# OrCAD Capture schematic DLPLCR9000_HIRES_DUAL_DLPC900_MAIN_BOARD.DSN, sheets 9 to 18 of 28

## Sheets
9 P21-Slave GPIOs: size A3
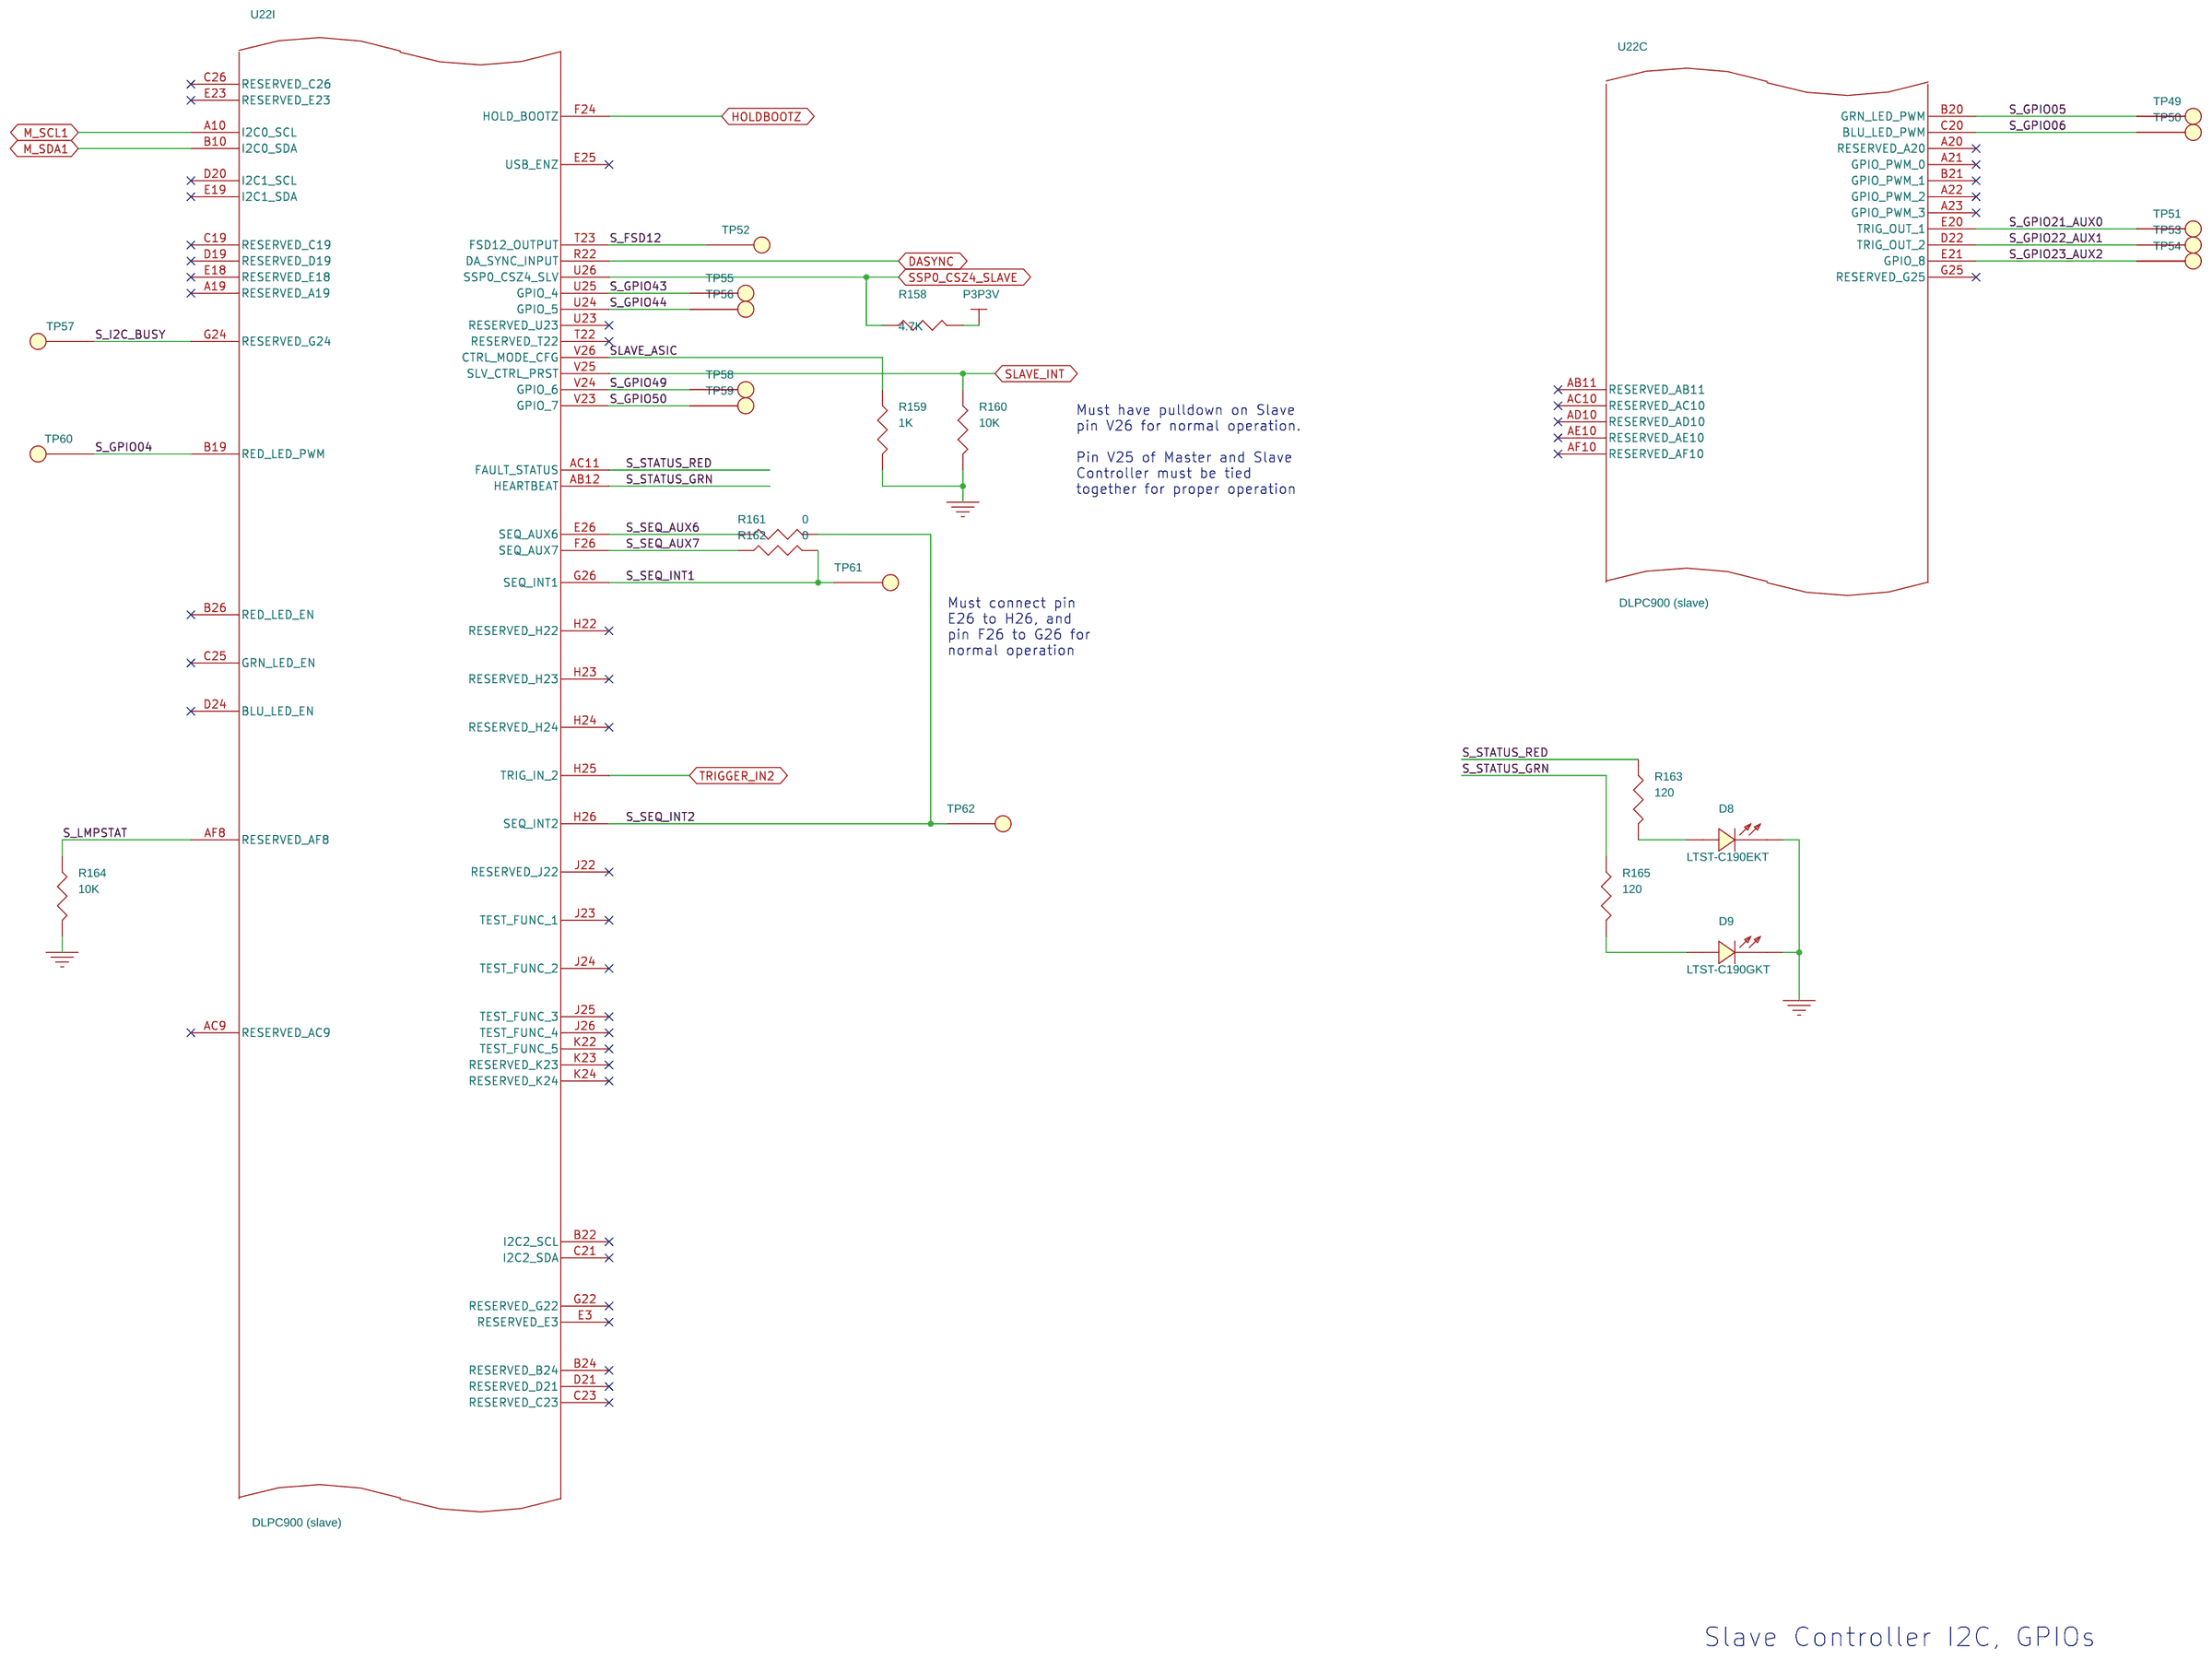
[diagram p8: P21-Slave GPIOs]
10 P19-Slave JTAG Osc Rst SSP: size A3
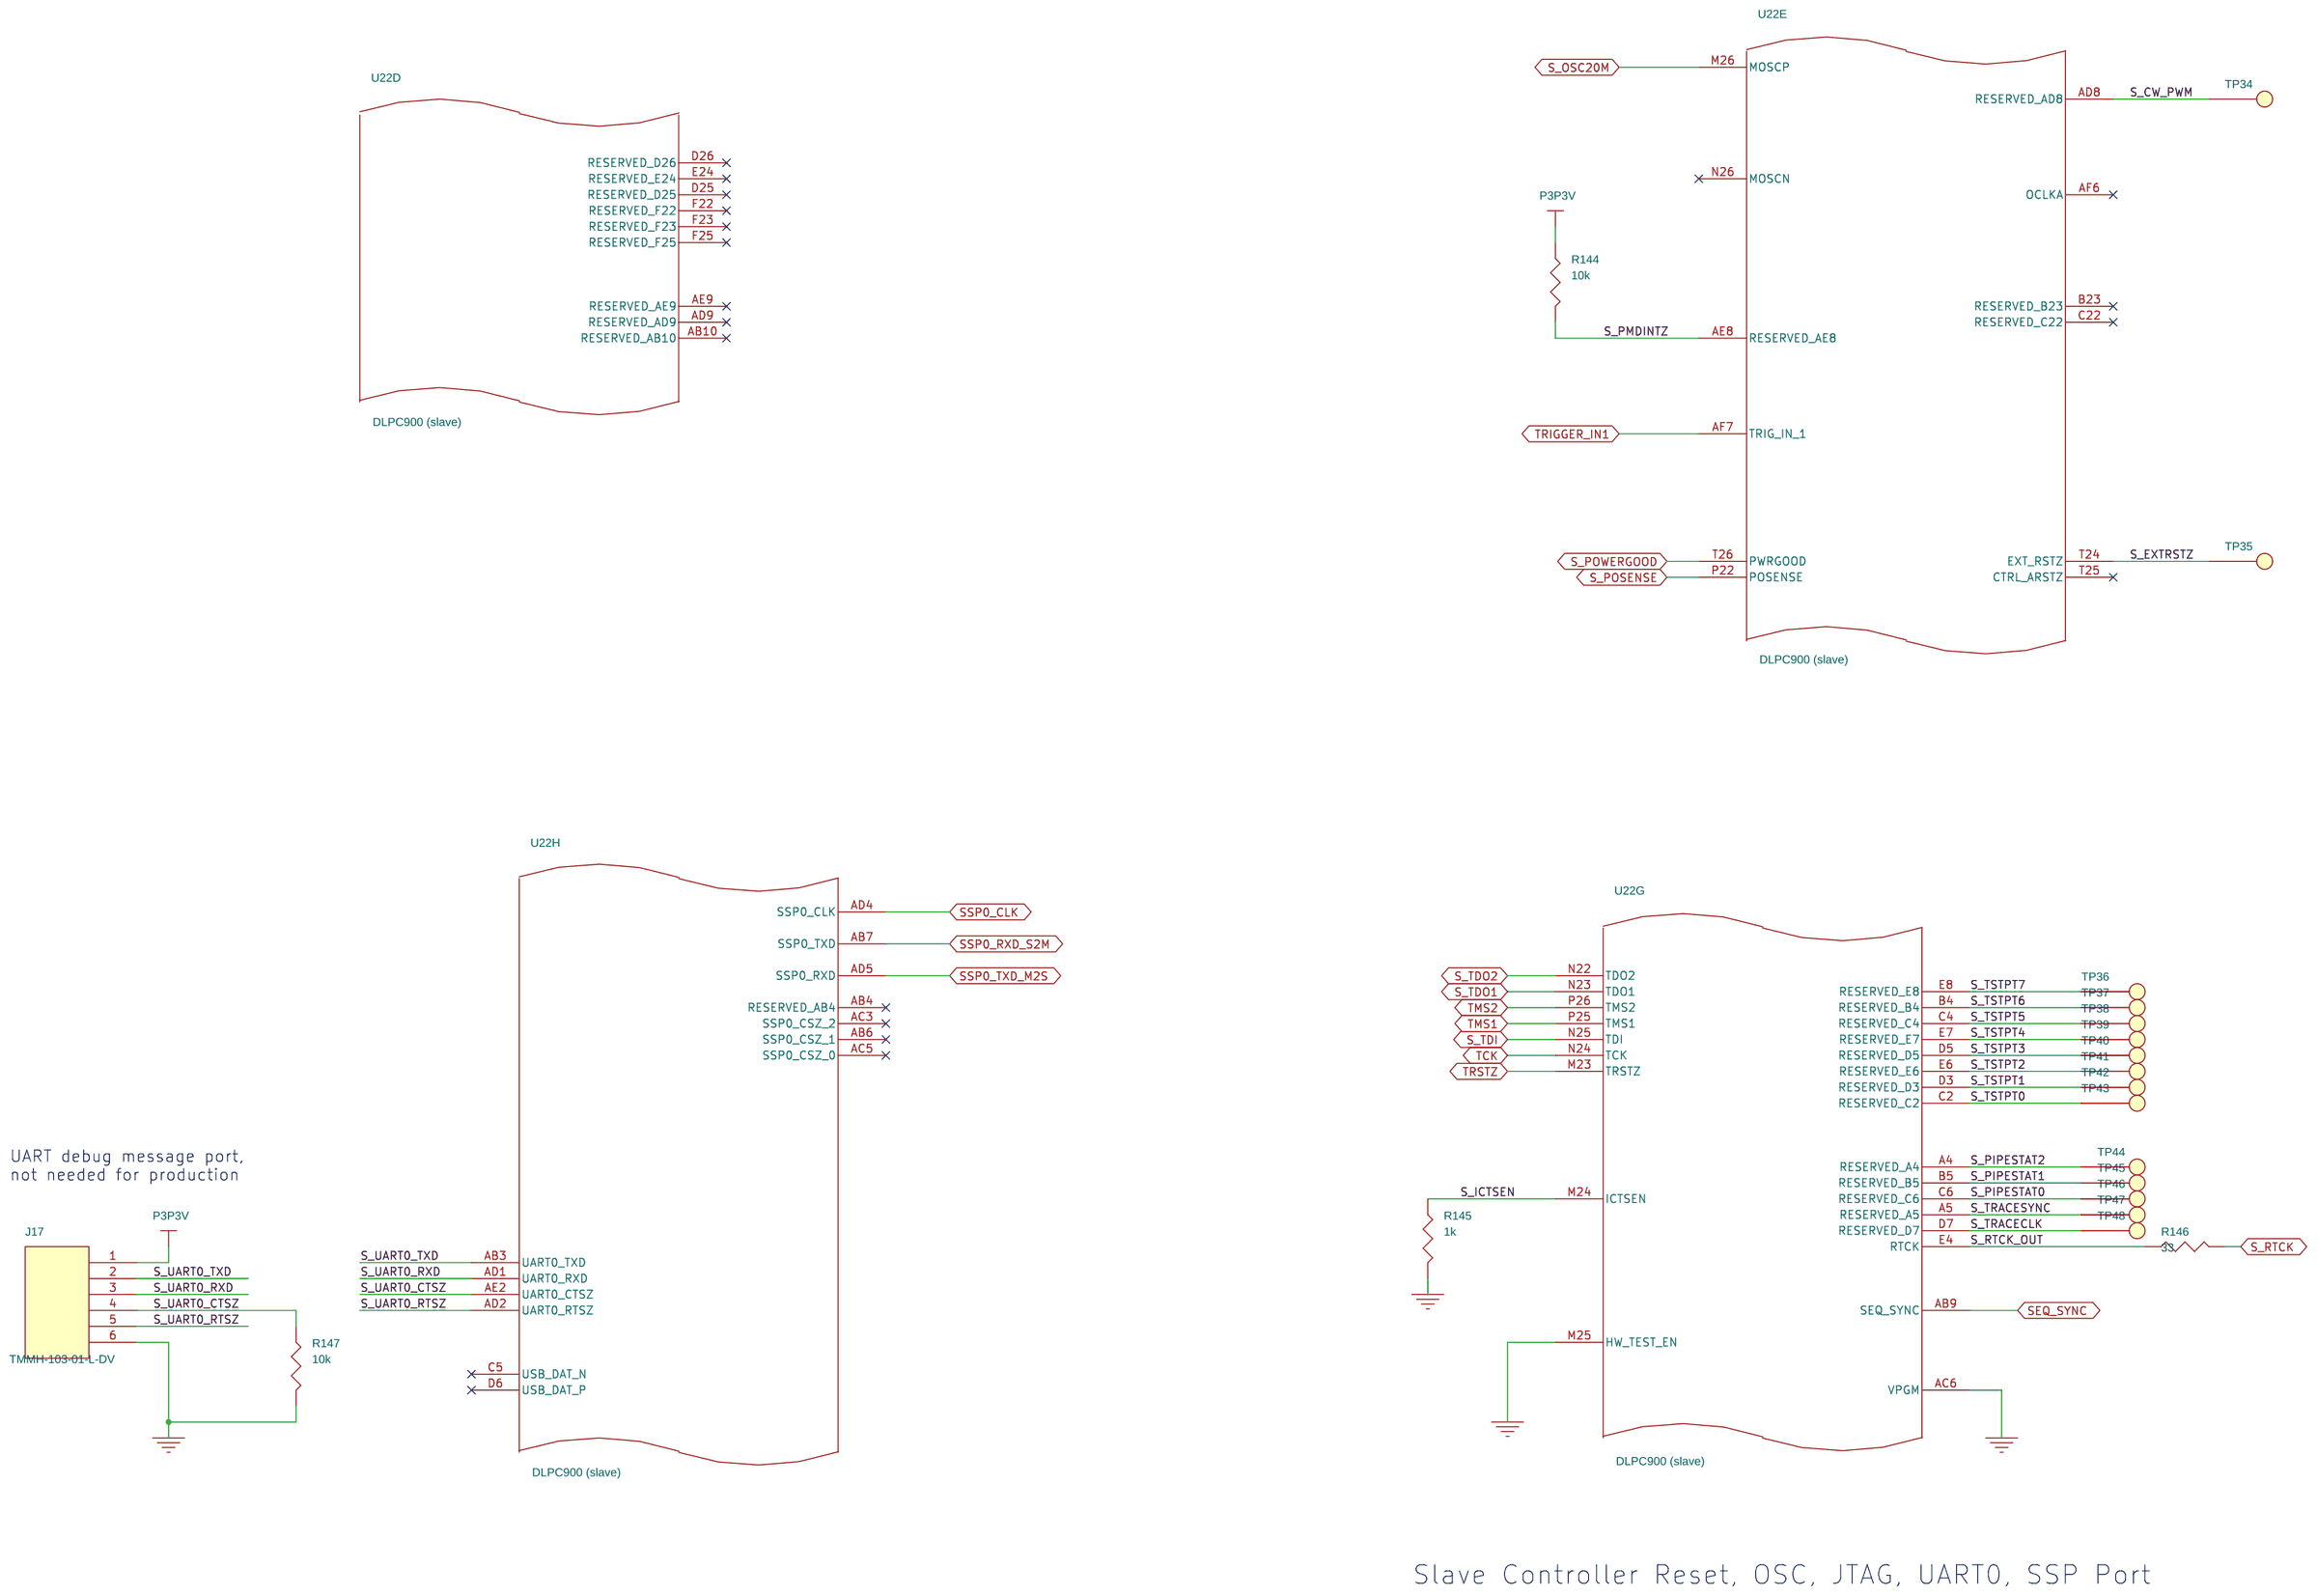
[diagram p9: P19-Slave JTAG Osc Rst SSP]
11 P18-Slave Vid DMD io: size A3
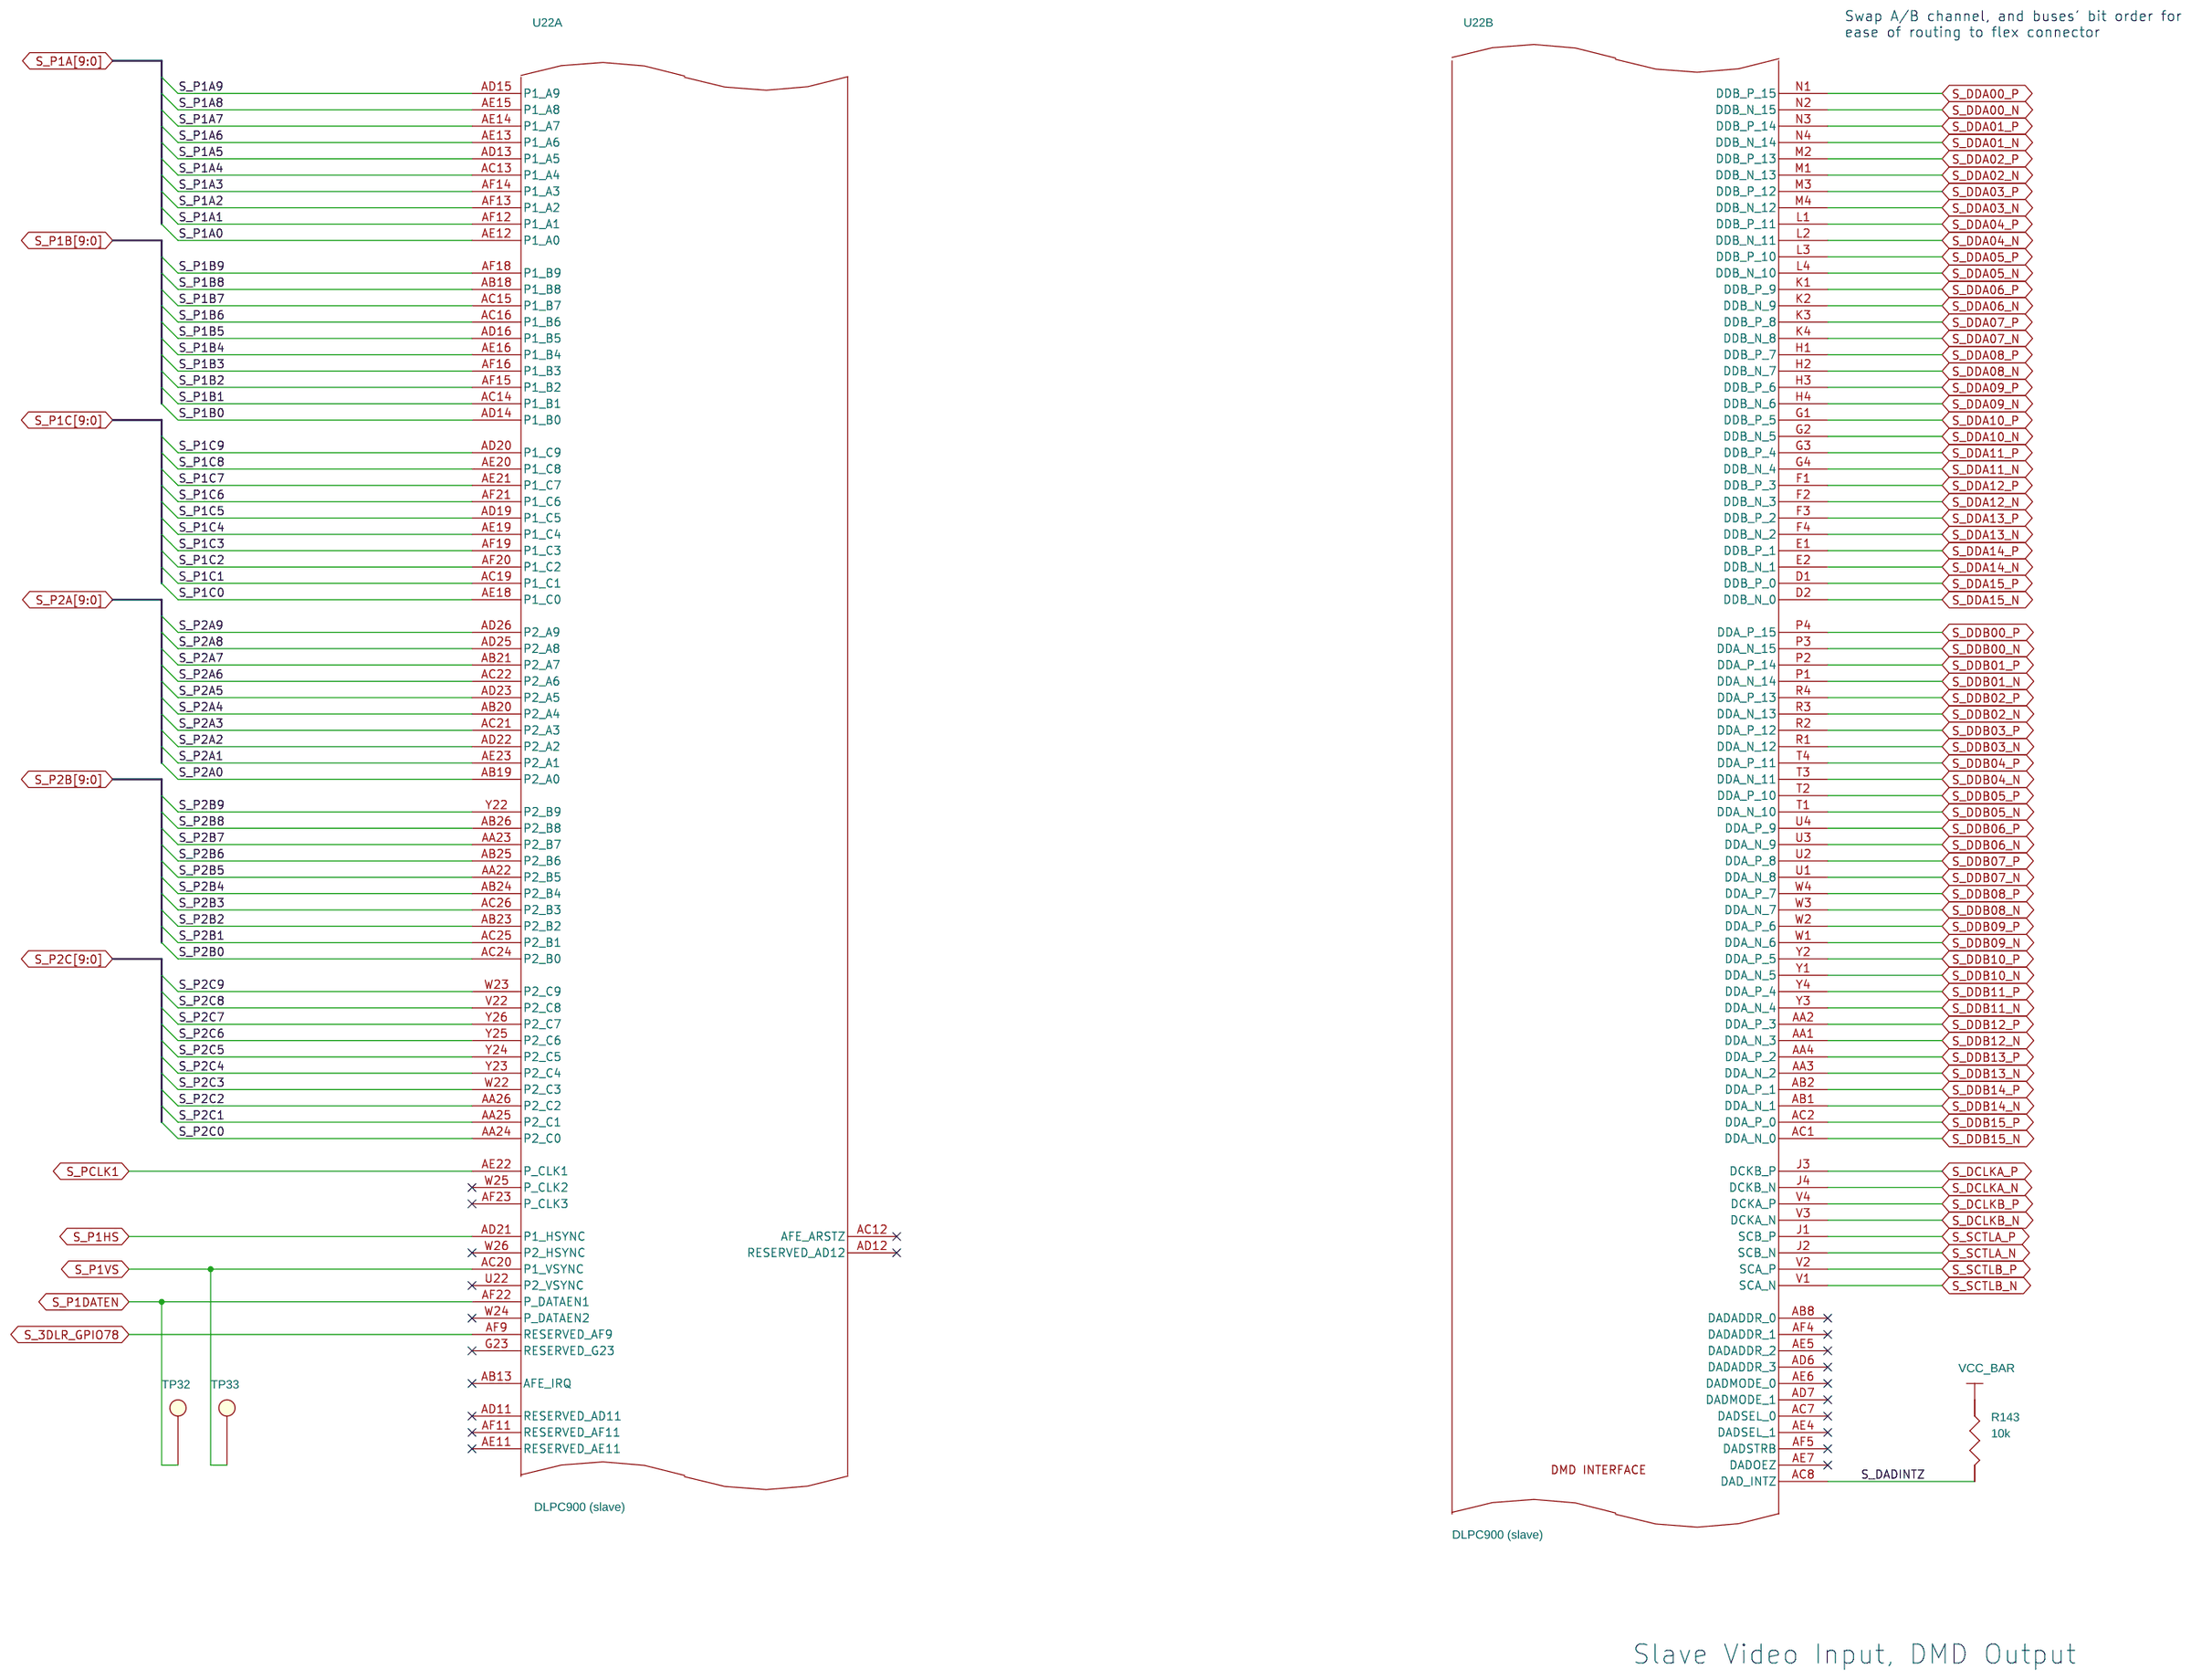
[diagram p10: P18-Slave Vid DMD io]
12 P26-Inout Trigger, LED Driver: size A3
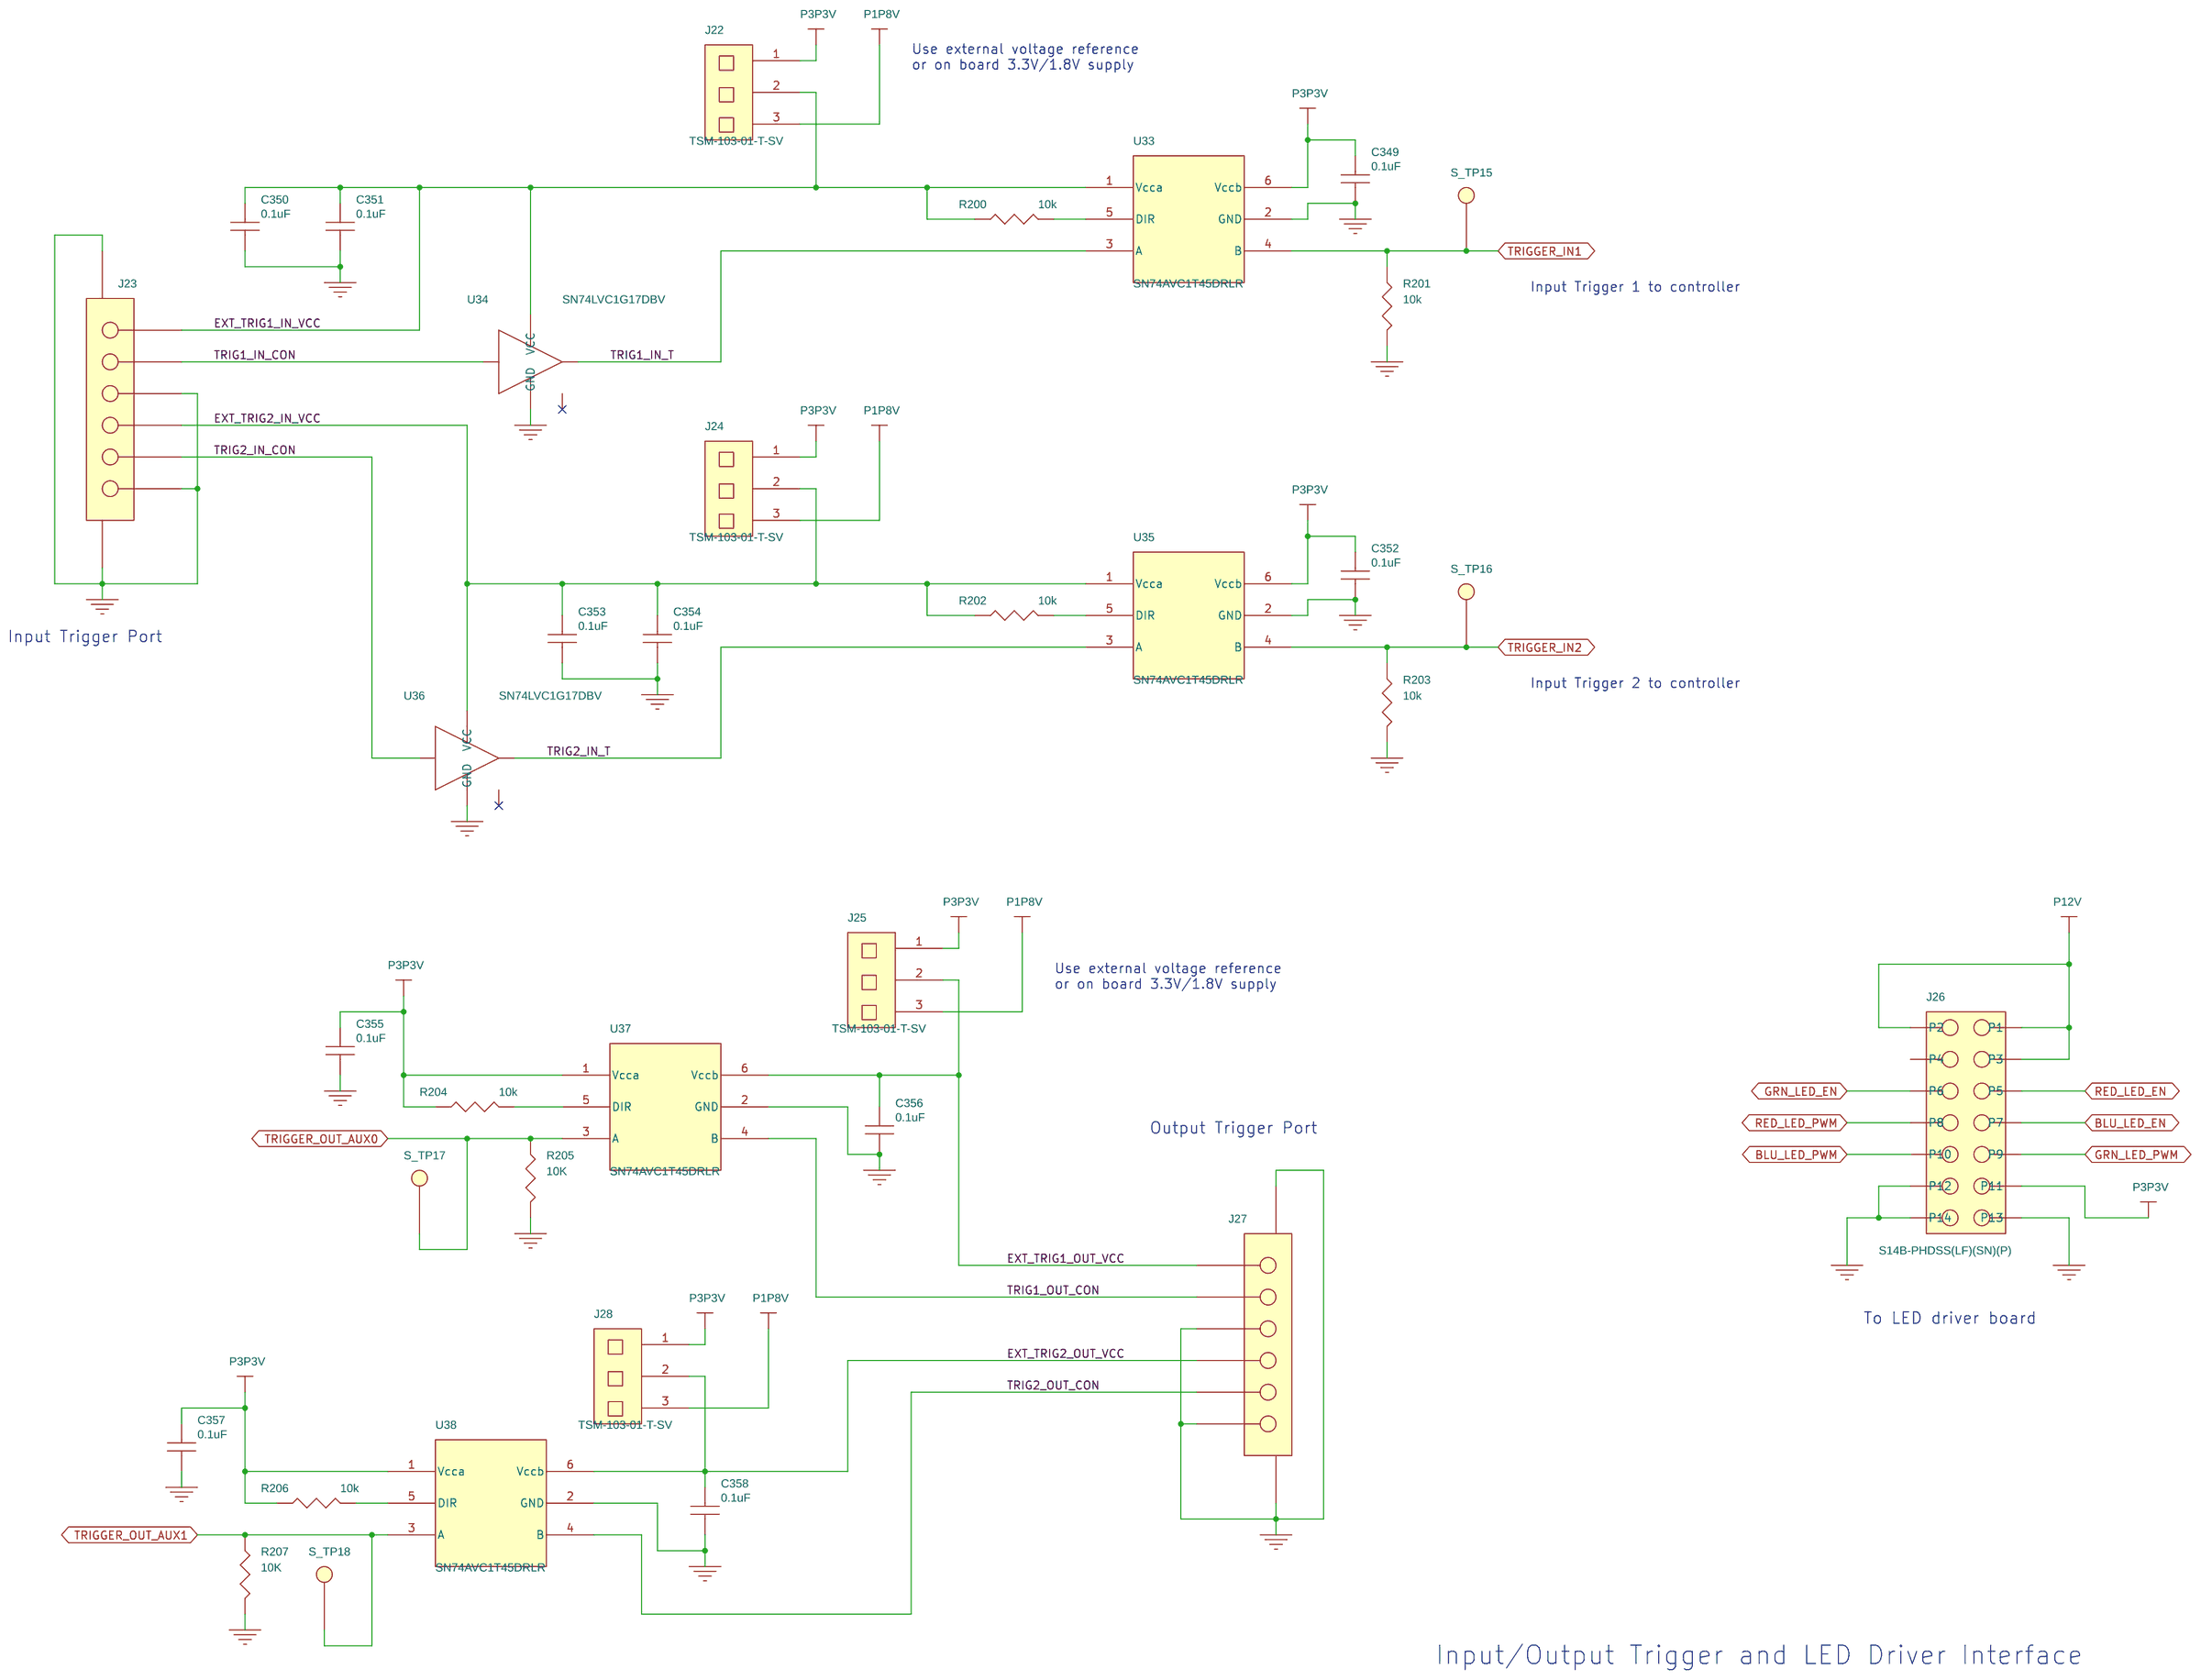
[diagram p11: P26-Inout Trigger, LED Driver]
13 P27-Gen pwrgood posense clk: size A3
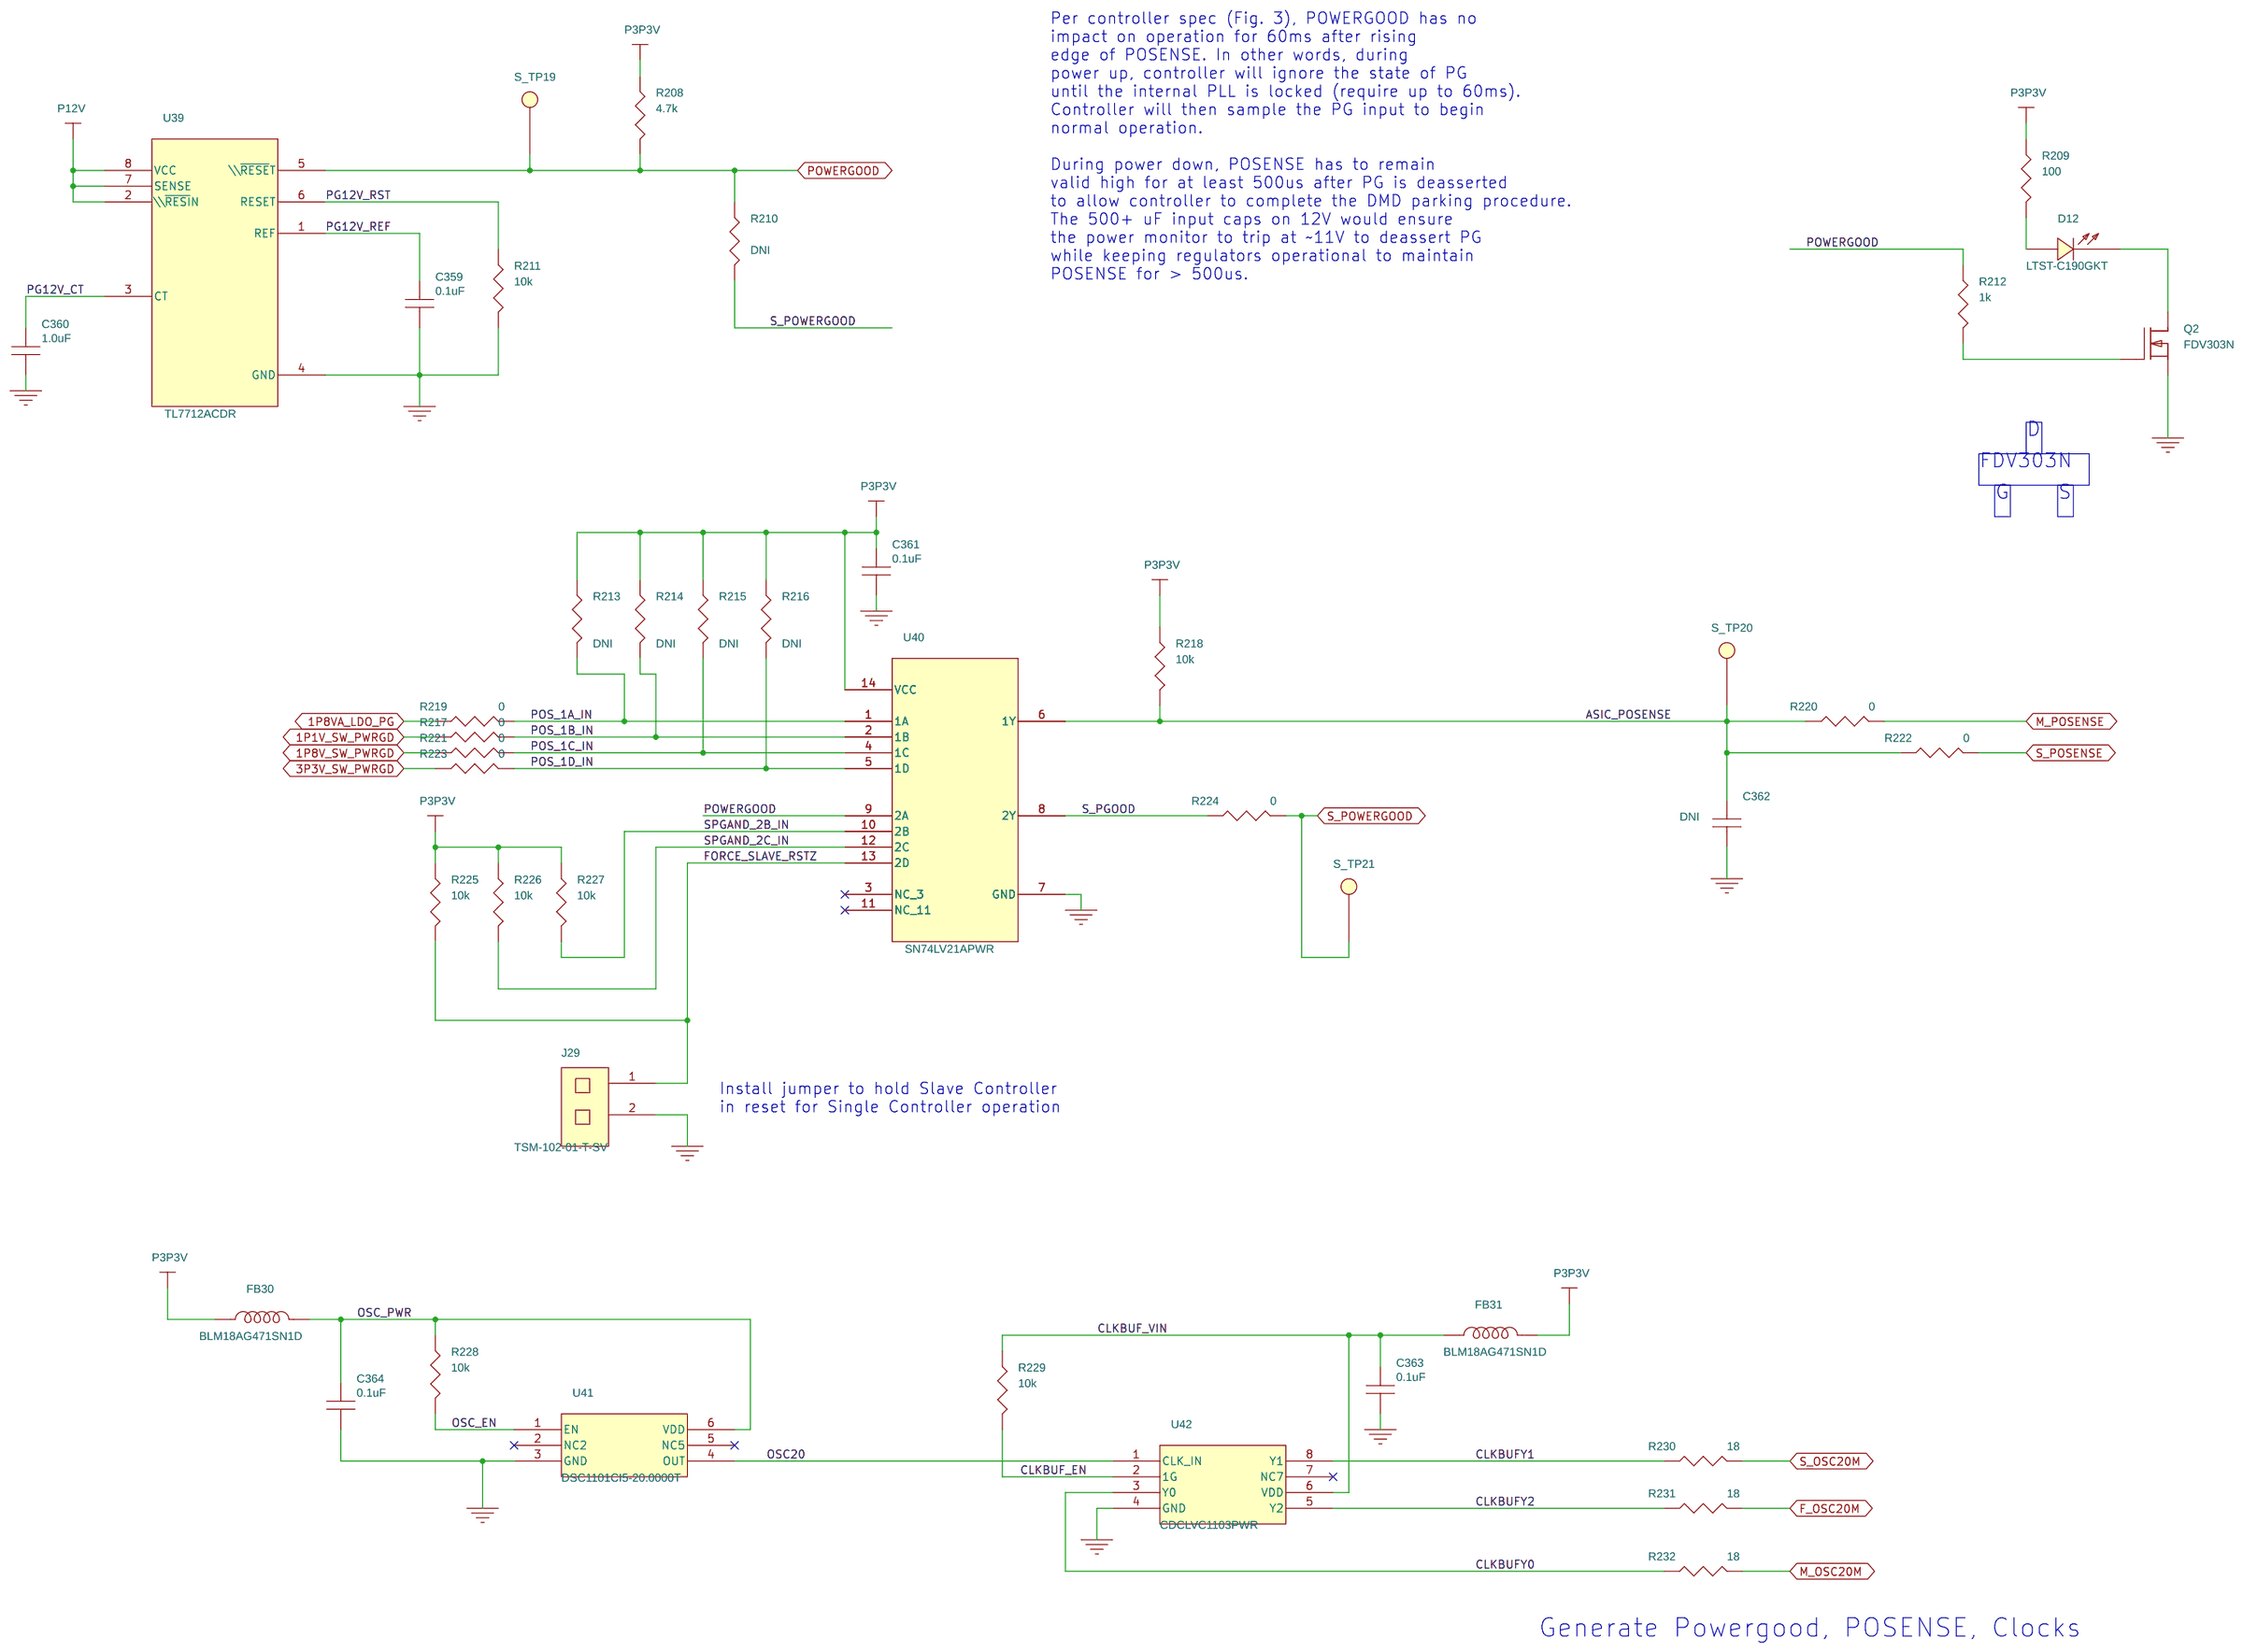
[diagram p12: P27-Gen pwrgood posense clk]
14 P16-Master I2C Trig GPIO: size A3
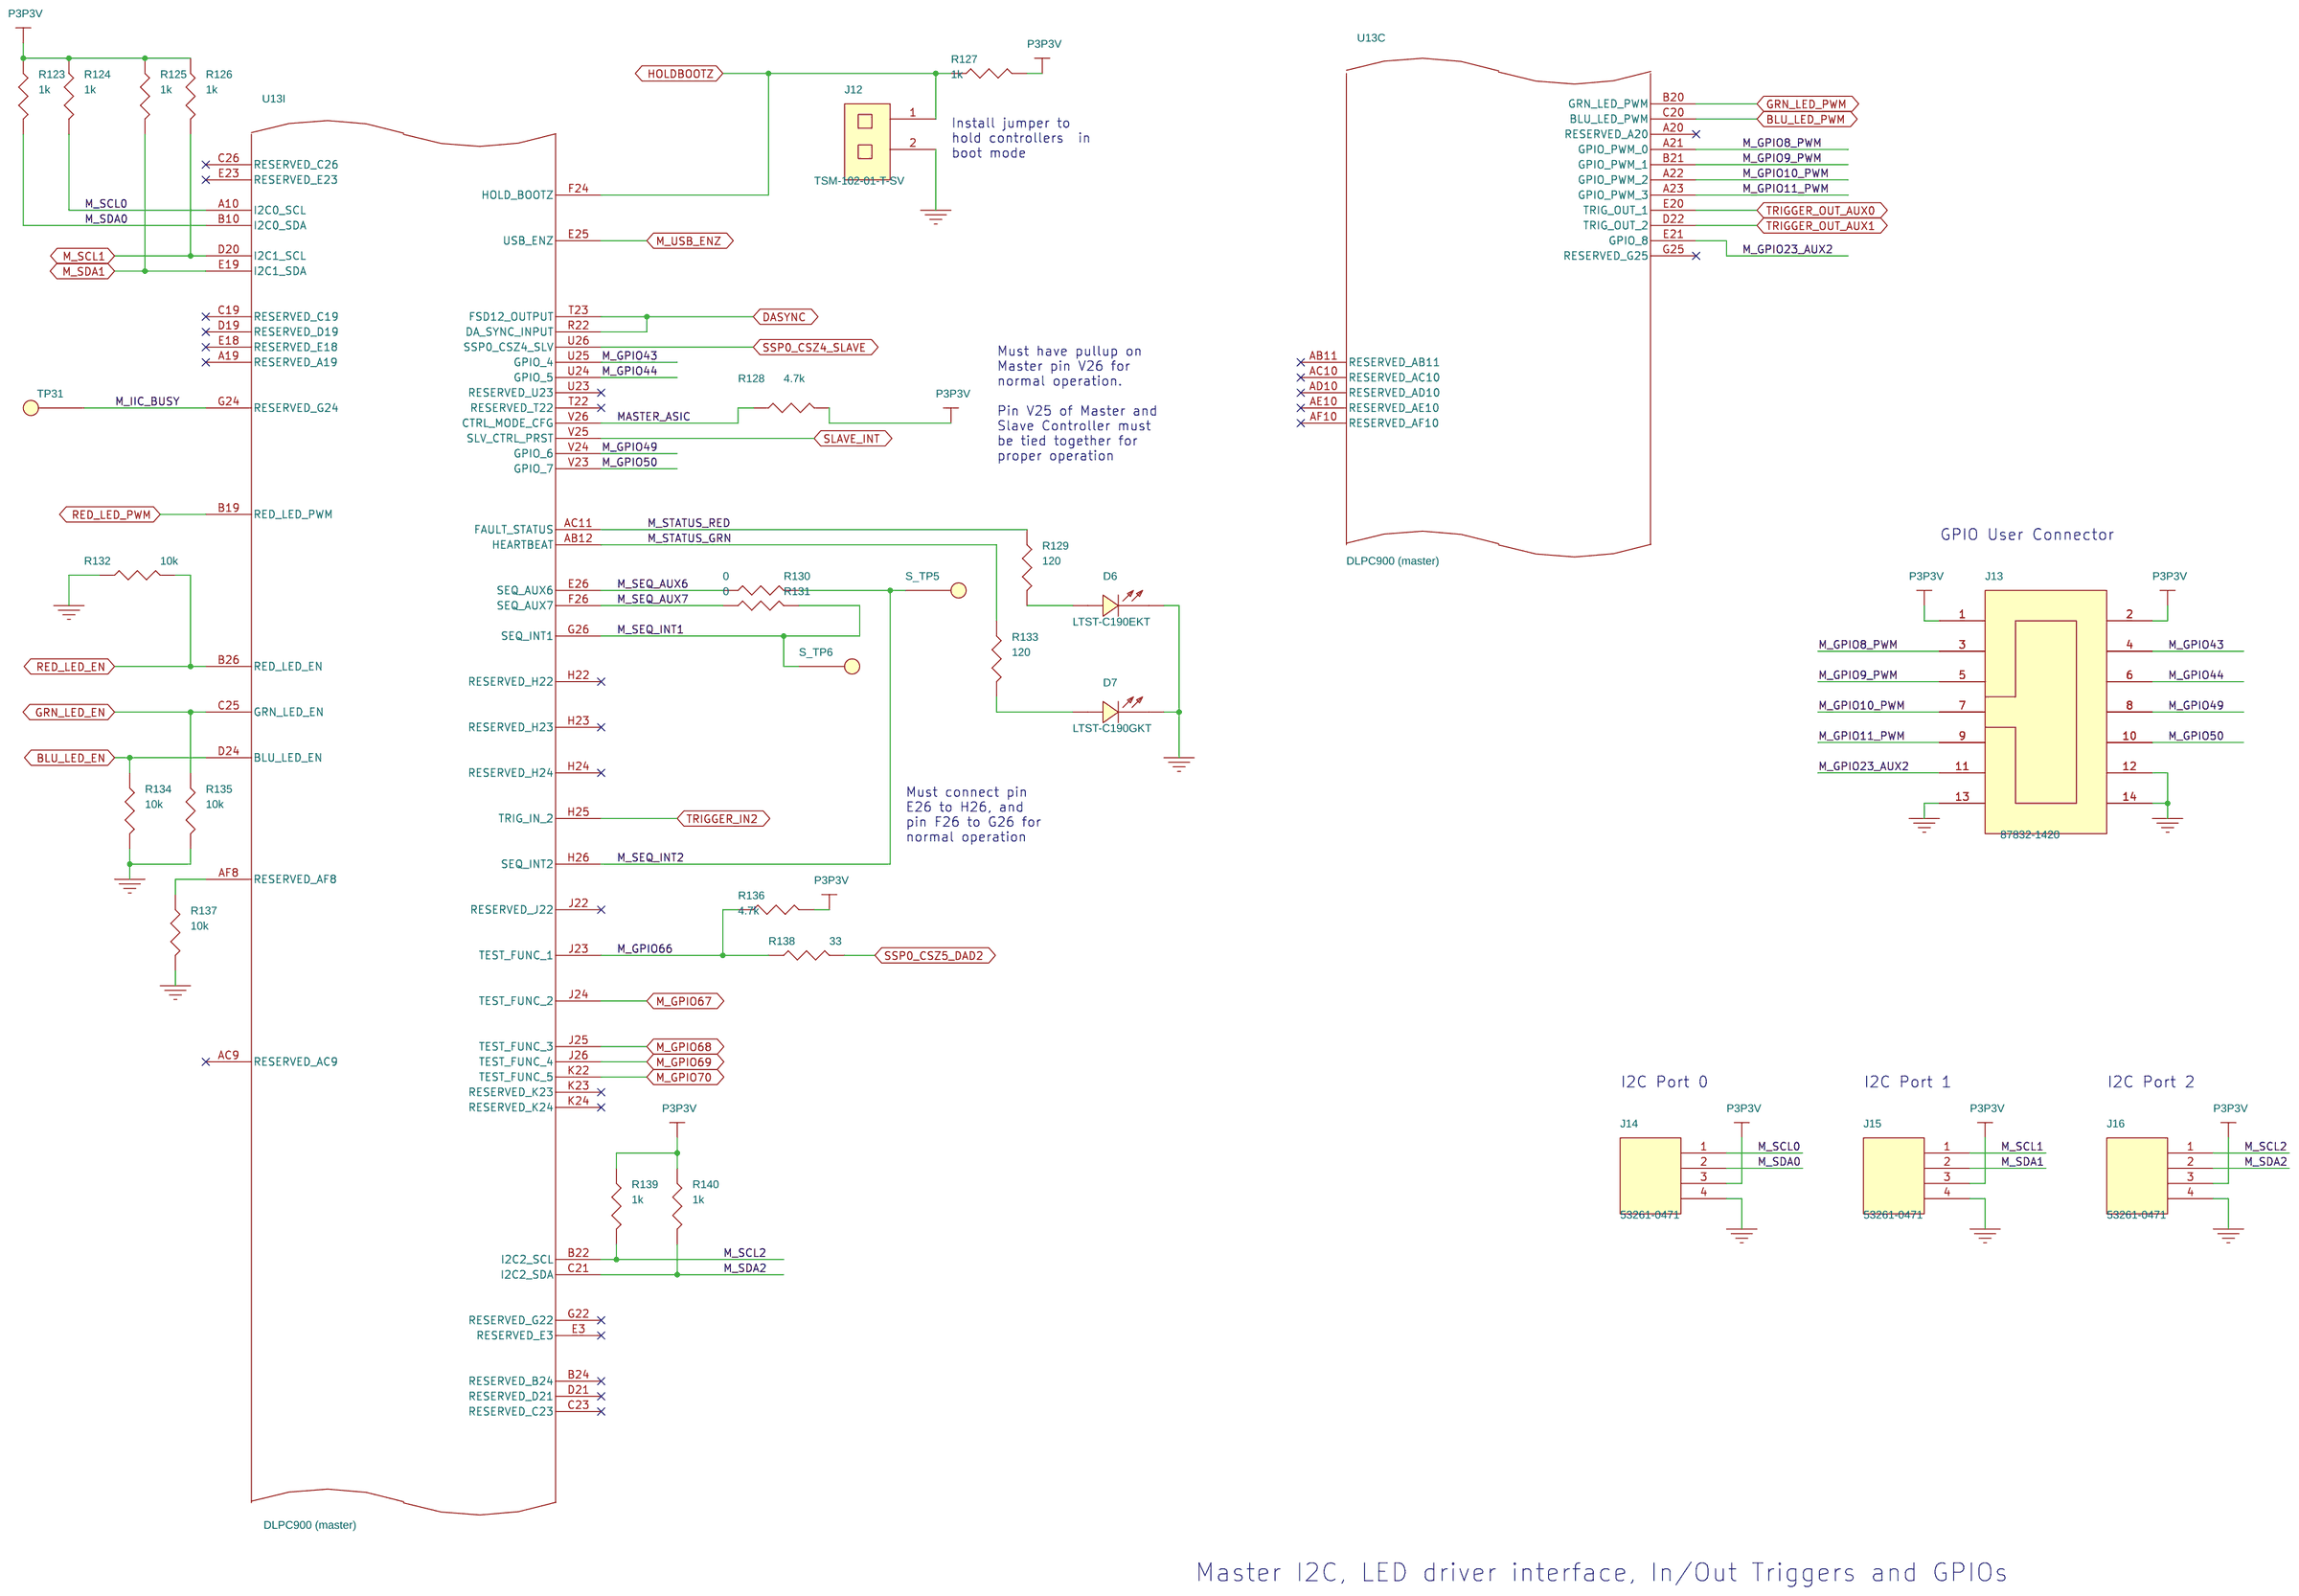
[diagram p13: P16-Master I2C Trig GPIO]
15 P15-Master ICE JTAG: size A3
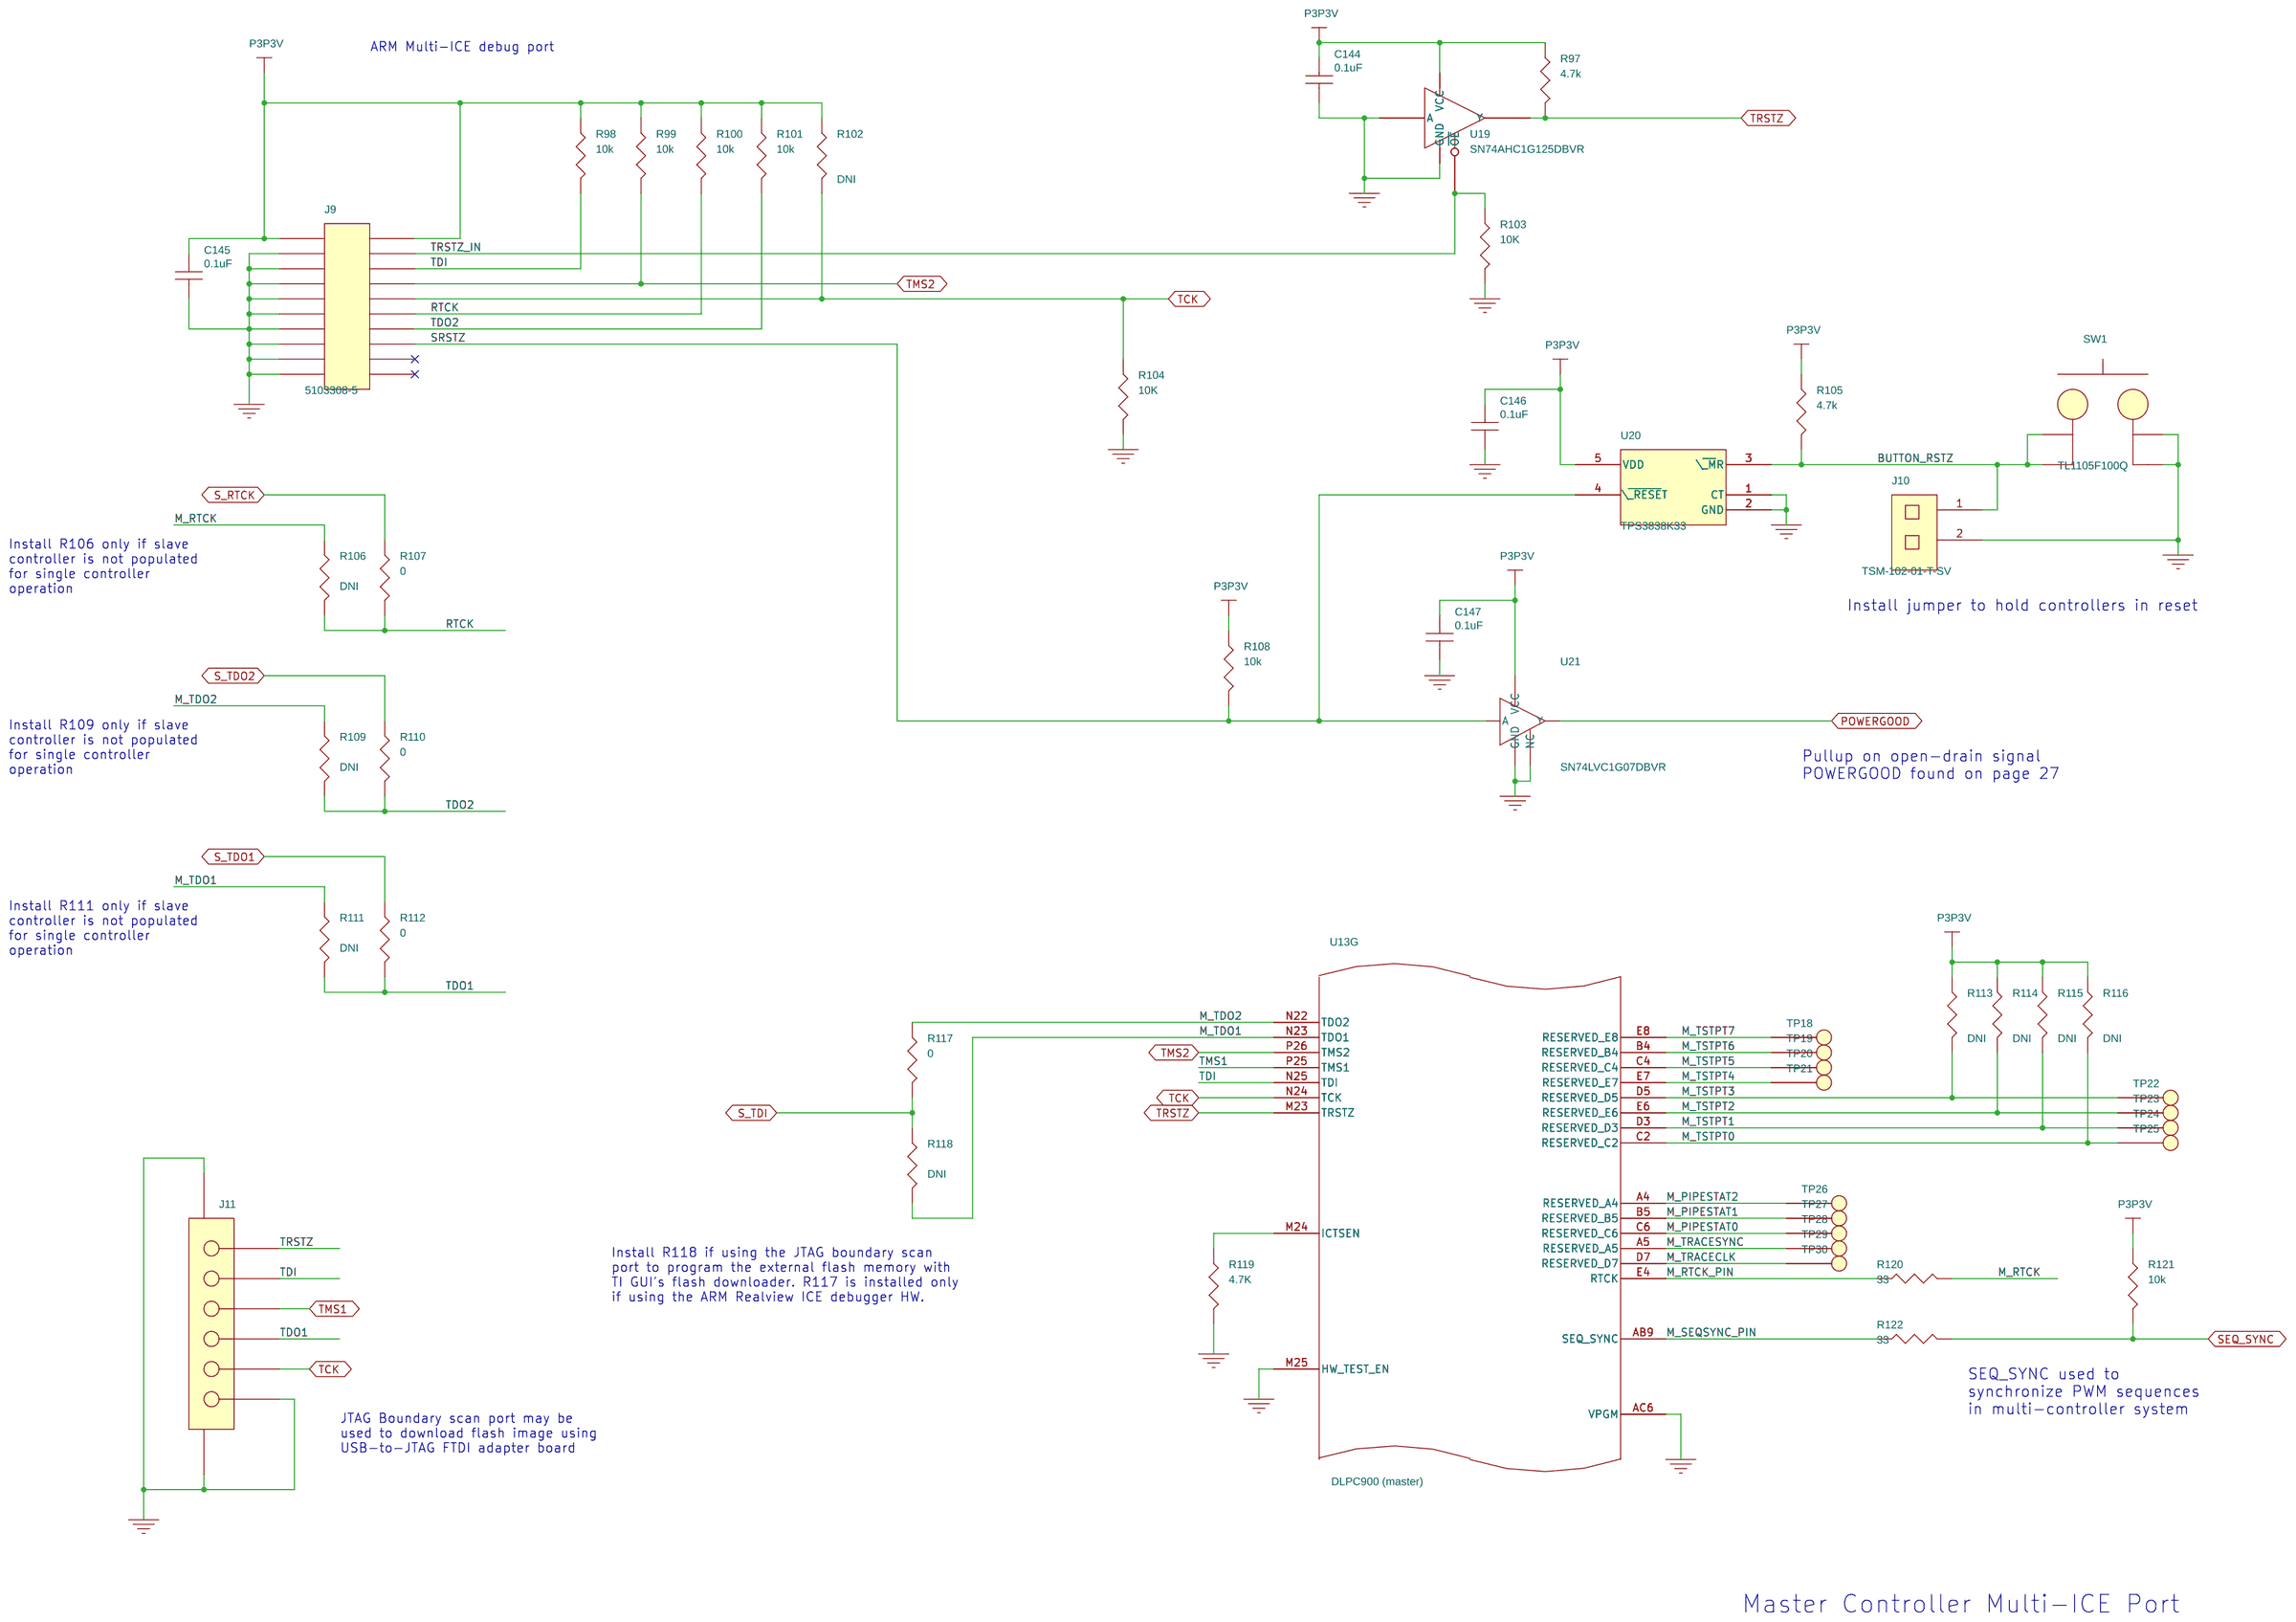
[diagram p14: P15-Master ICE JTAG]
16 P14-Master Ext Flash Intf: size A3
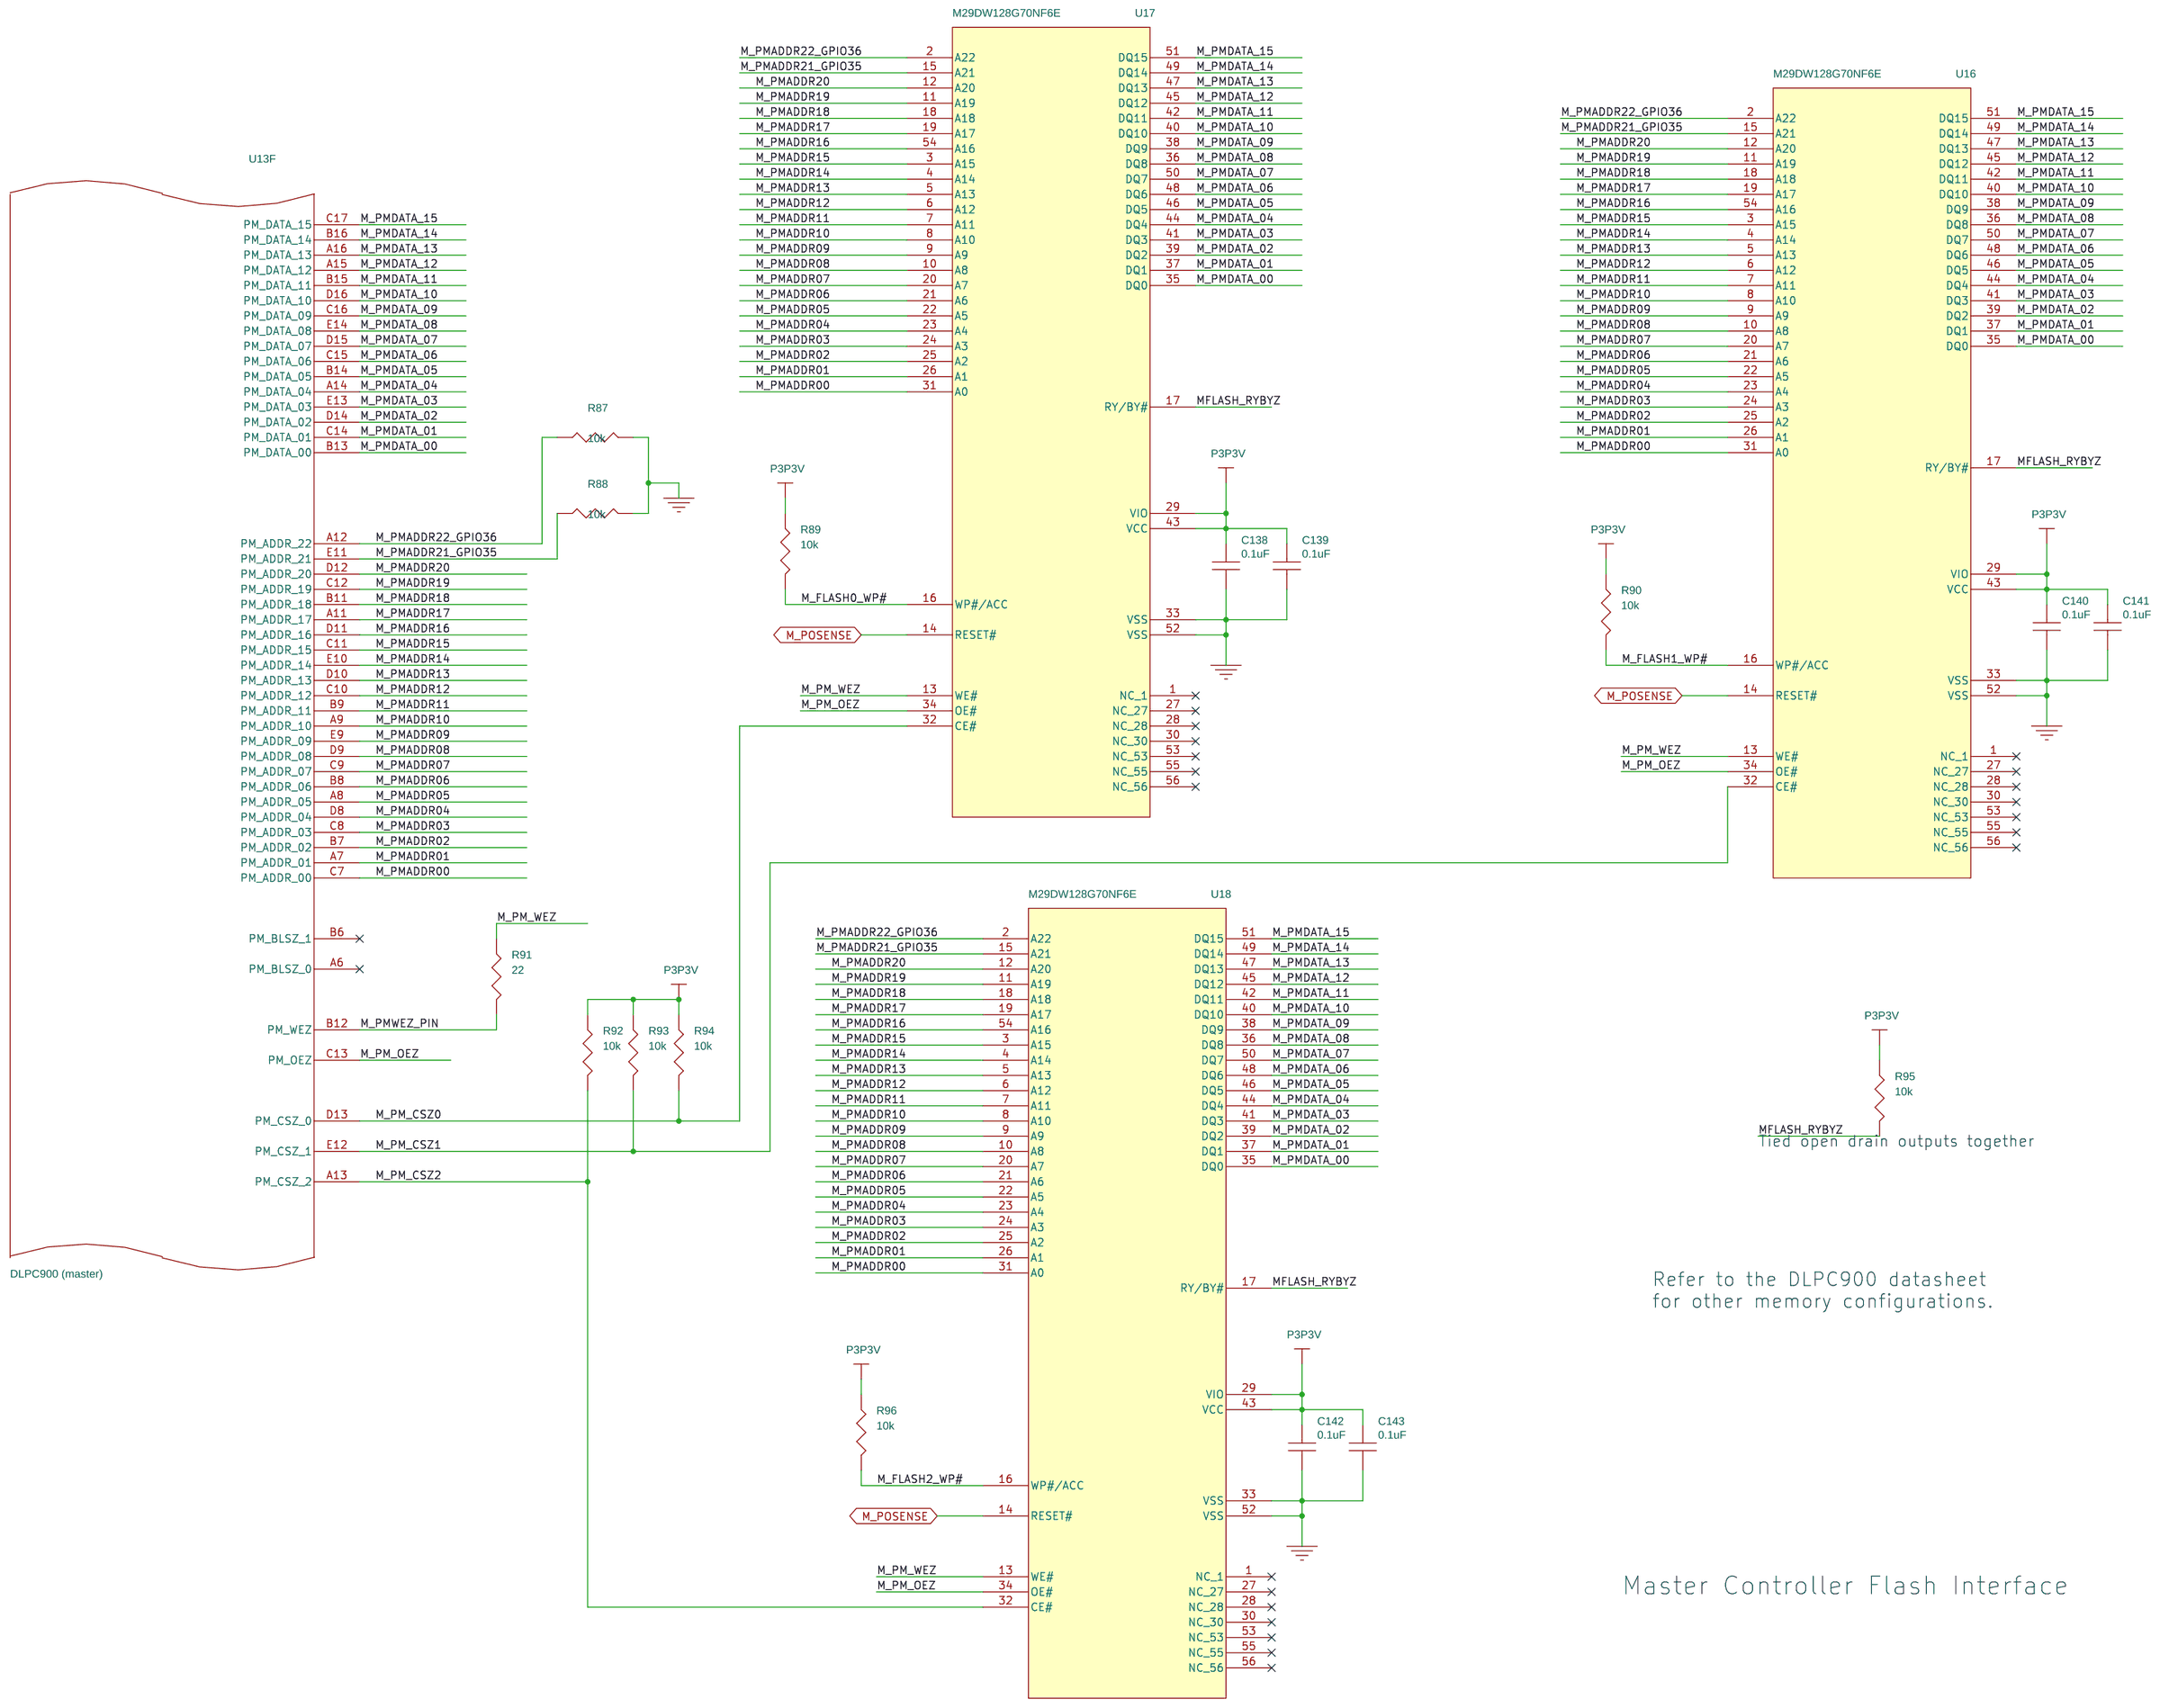
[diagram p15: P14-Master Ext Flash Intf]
17 P13-Master USB Osc Rst SSP: size A3
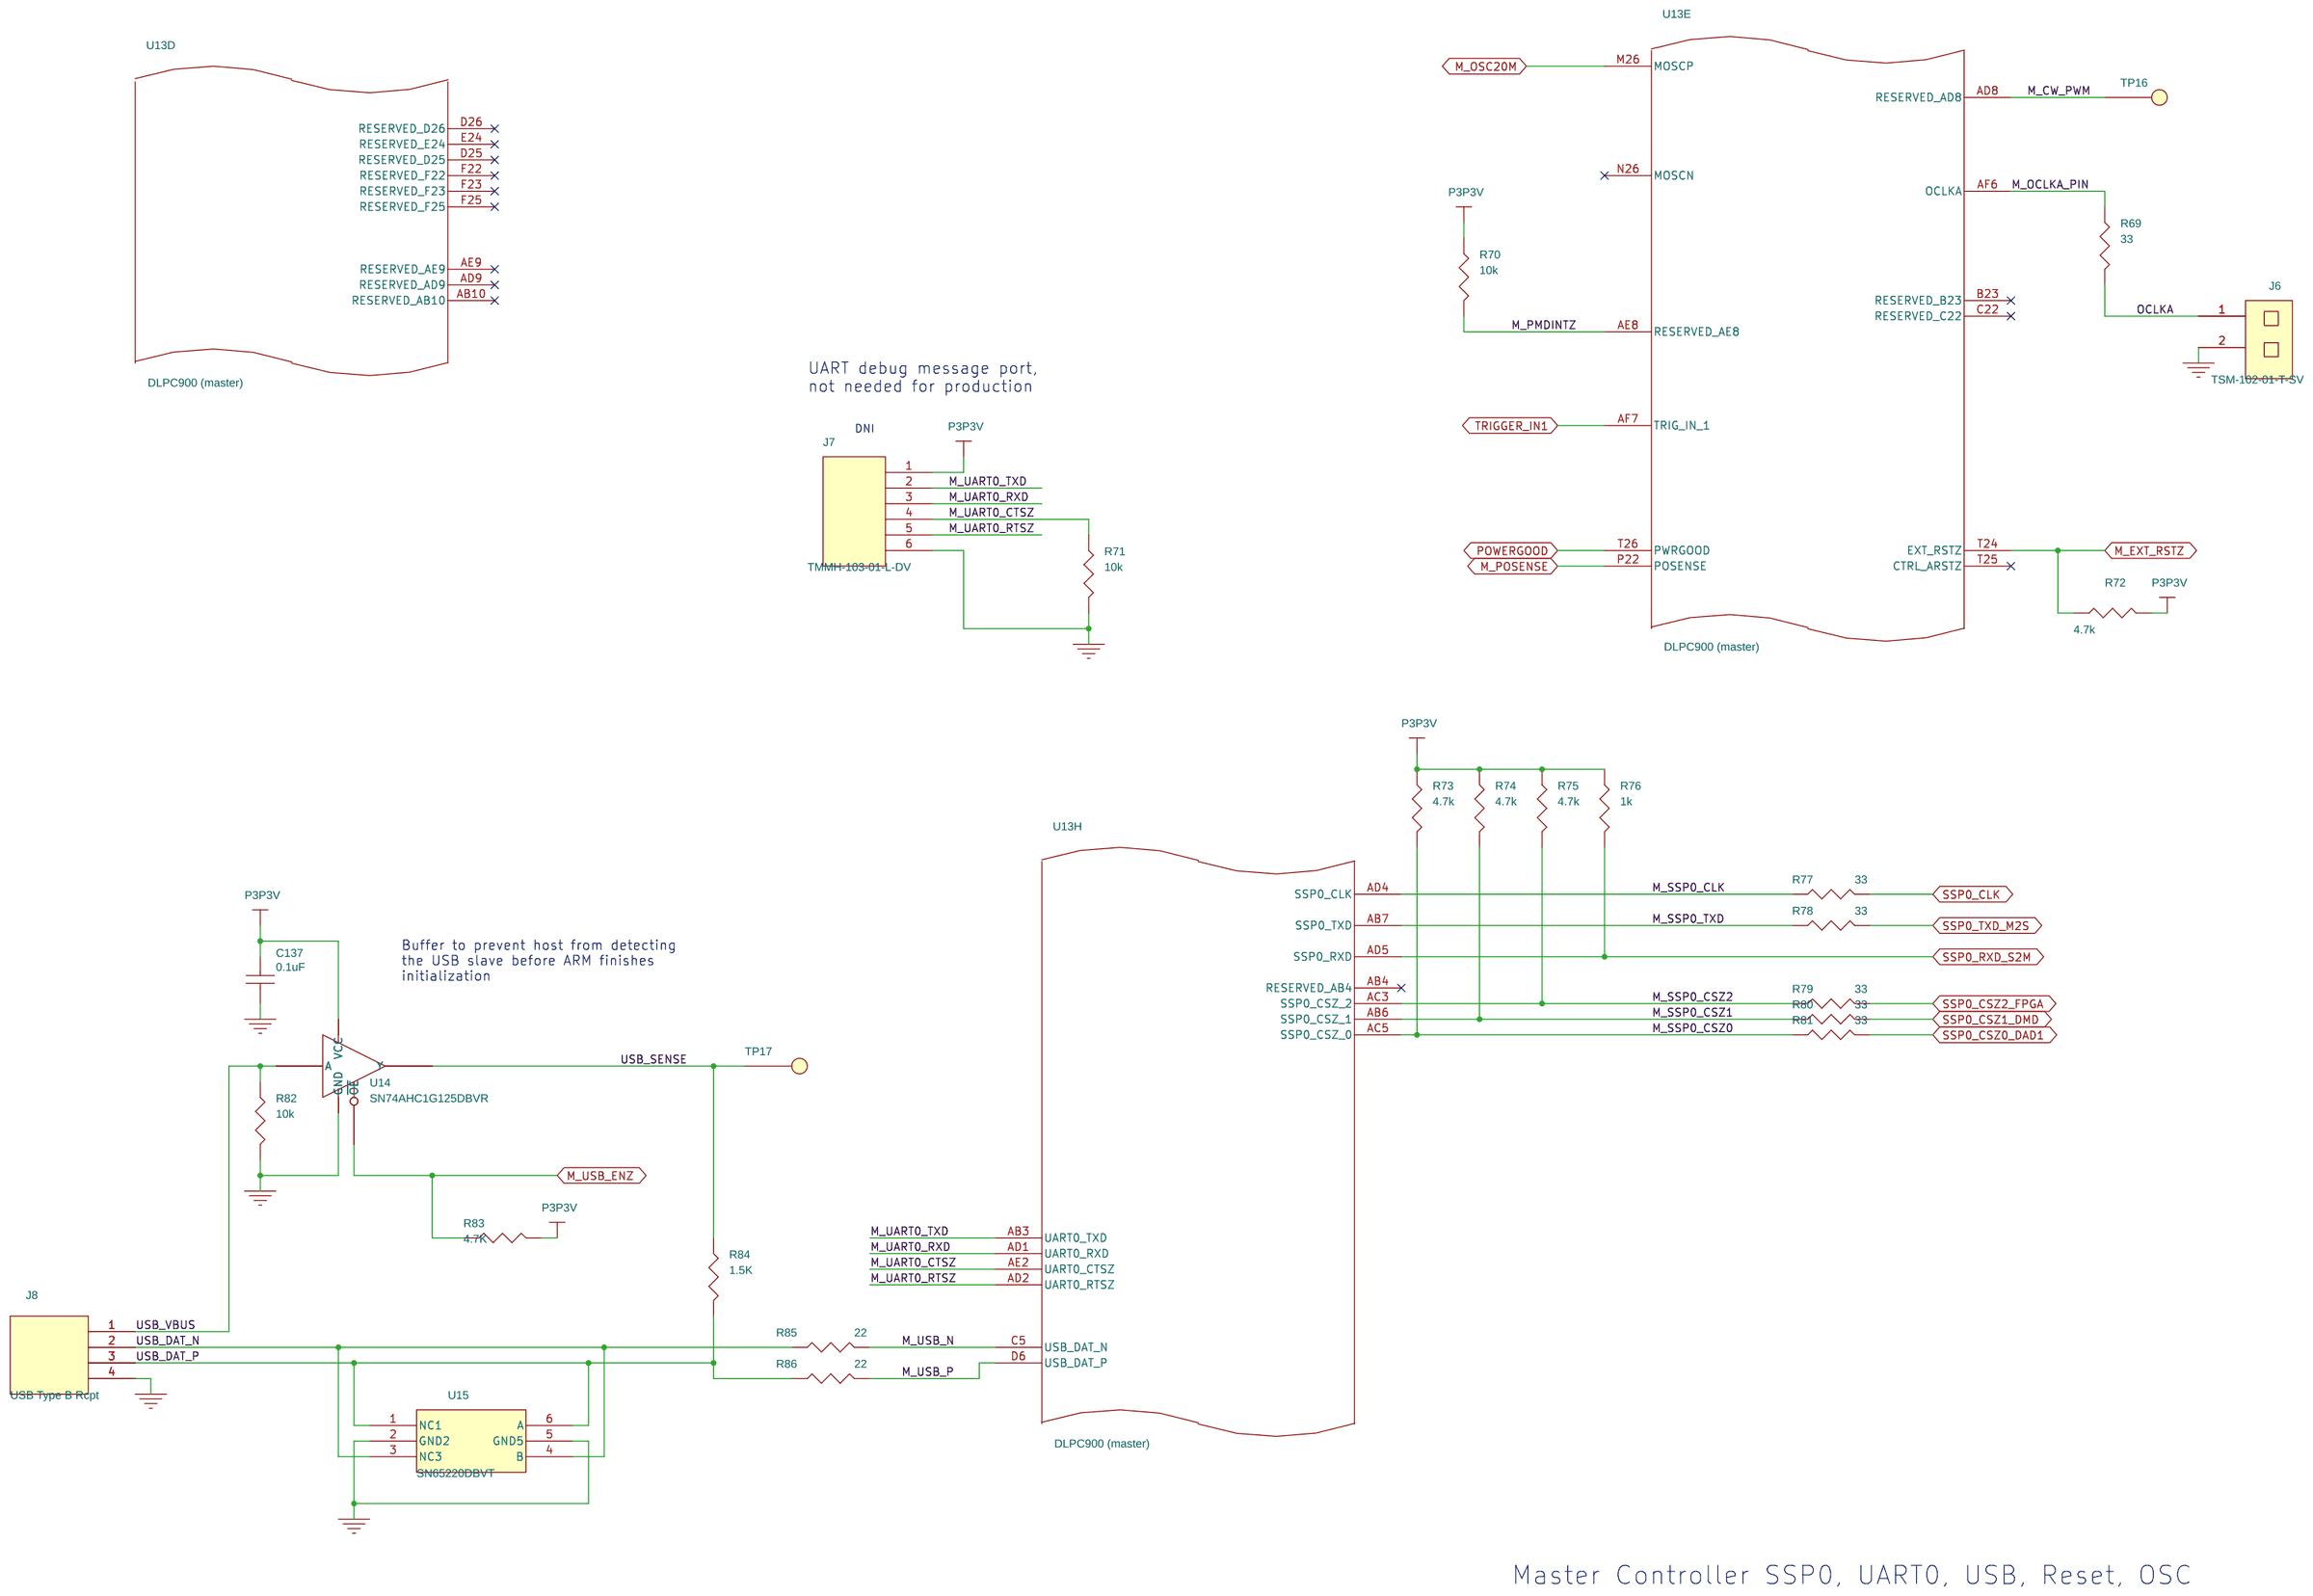
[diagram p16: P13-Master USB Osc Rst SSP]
18 P12-Master Vid DMD DAD io: size A3
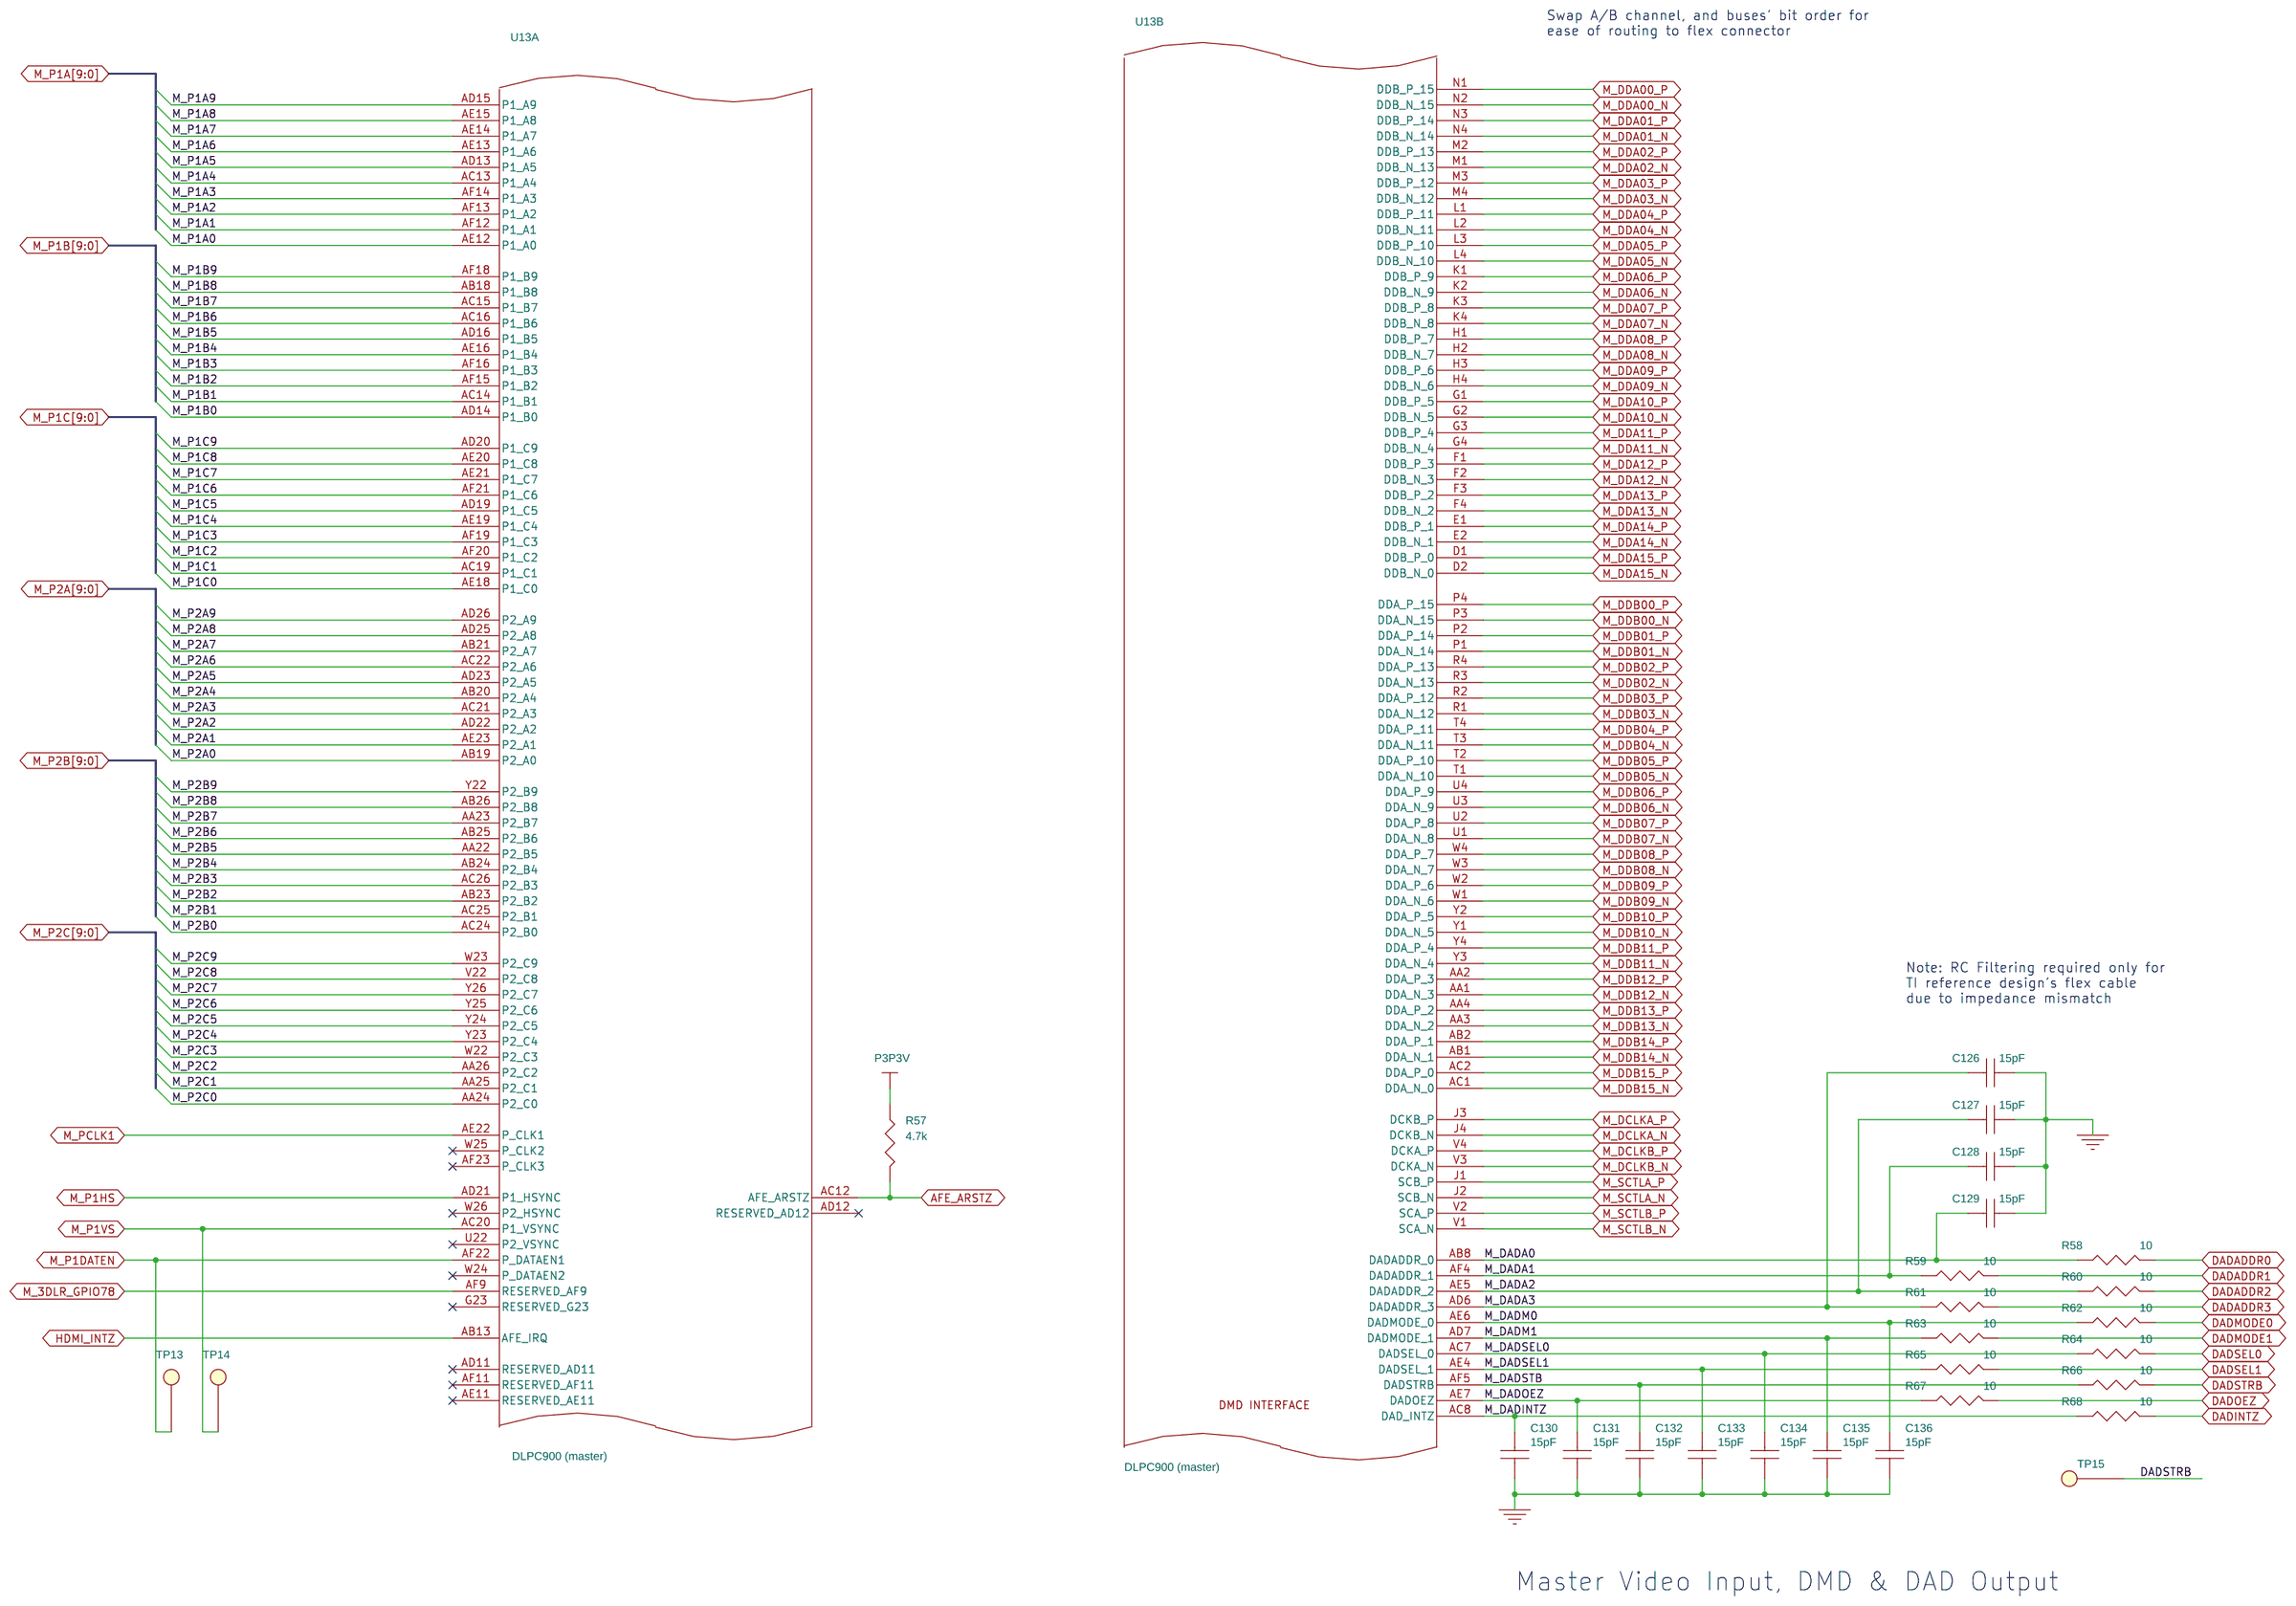
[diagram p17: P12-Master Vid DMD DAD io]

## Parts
sheet P12-Master Vid DMD DAD io
C126  15pF  [0402]
C127  15pF  [0402]
C128  15pF  [0402]
C129  15pF  [0402]
C130  15pF  [0402]
C131  15pF  [0402]
C132  15pF  [0402]
C133  15pF  [0402]
C134  15pF  [0402]
C135  15pF  [0402]
C136  15pF  [0402]
R57  4.7k  [0402]
R58  10  [0402]
R59  10  [0402]
R60  10  [0402]
R61  10  [0402]
R62  10  [0402]
R63  10  [0402]
R64  10  [0402]
R65  10  [0402]
R66  10  [0402]
R67  10  [0402]
R68  10  [0402]
TP13  Testpoint  [24mil-plated]
TP14  Testpoint  [24mil-plated]
TP15  Testpoint  [24mil-plated]
sheet P13-Master USB Osc Rst SSP
C137  0.1uF  [0402]
J6  TSM-102-01-T-SV  [2POS-2p54mm]
J7  TMMH-103-01-L-DV  [6POS-2ROWS-2mm]
J8  USB Type B Rcpt  [4thruhole]
R69  33  [0603]
R70  10k  [0402]
R71  10k  [0402]
R72  4.7k  [0402]
R73  4.7k  [0402]
R74  4.7k  [0402]
R75  4.7k  [0402]
R76  1k  [0603]
R77  33  [0603]
R78  33  [0603]
R79  33  [0603]
R80  33  [0603]
R81  33  [0603]
R82  10k  [0603]
R83  4.7K  [0402]
R84  1.5K  [0603]
R85  22  [2010]
R86  22  [2010]
TP16  Testpoint  [24mil-plated]
TP17  Testpoint  [24mil-plated]
U14  SN74AHC1G125DBVR  [SOT235]
U15  SN65220DBVT  [SOT23-6]
sheet P14-Master Ext Flash Intf
C138  0.1uF  [0402]
C139  0.1uF  [0402]
C140  0.1uF  [0402]
C141  0.1uF  [0402]
C142  0.1uF  [0402]
C143  0.1uF  [0402]
R87  10k  [0402]
R88  10k  [0402]
R89  10k  [0402]
R90  10k  [0402]
R91  22  [0402]
R92  10k  [0402]
R93  10k  [0402]
R94  10k  [0402]
R95  10k  [0402]
R96  10k  [0402]
U16  M29DW128G70NF6E  [56TSOP]
U17  M29DW128G70NF6E  [56TSOP]
U18  M29DW128G70NF6E  [56TSOP]
sheet P15-Master ICE JTAG
C144  0.1uF  [0402]
C145  0.1uF  [0402]
C146  0.1uF  [0402]
C147  0.1uF  [0402]
J9  5103308-5  [2x10Pos]
J10  TSM-102-01-T-SV  [2POS-2p54mm]
J11  0532610671  [6pos_1p25mm]
R97  4.7k  [0402]
R98  10k  [0402]
R99  10k  [0402]
R100  10k  [0402]
R101  10k  [0402]
R102  DNI  [0402]
R103  10K  [0402]
R104  10K  [0402]
R105  4.7k  [0402]
R106  DNI  [0603]
R107  0  [0603]
R108  10k  [0402]
R109  DNI  [0603]
R110  0  [0603]
R111  DNI  [0603]
R112  0  [0603]
R113  DNI  [0402]
R114  DNI  [0402]
R115  DNI  [0402]
R116  DNI  [0402]
R117  0  [0603]
R118  DNI  [0603]
R119  4.7K  [0402]
R120  33  [0603]
R121  10k  [0402]
R122  33  [0603]
SW1  TL1105F100Q  [6x6mm]
TP18  Testpoint  [24mil-plated]
TP19  Testpoint  [24mil-plated]
TP20  Testpoint  [24mil-plated]
TP21  Testpoint  [24mil-plated]
TP22  Testpoint  [24mil-plated]
TP23  Testpoint  [24mil-plated]
TP24  Testpoint  [24mil-plated]
TP25  Testpoint  [24mil-plated]
TP26  Testpoint  [24mil-plated]
TP27  Testpoint  [24mil-plated]
TP28  Testpoint  [24mil-plated]
TP29  Testpoint  [24mil-plated]
TP30  Testpoint  [24mil-plated]
U13  DLPC900 (master)  [516BGA]  (sections A,B,C,D,E,F,G,H,I,J)
U19  SN74AHC1G125DBVR  [SOT235]
U20  TPS3838K33  [SOT23-5]
U21  SN74LVC1G07DBVR  [SOT235]
sheet P16-Master I2C Trig GPIO
D6  LTST-C190EKT  [0603]
D7  LTST-C190GKT  [0603]
J12  TSM-102-01-T-SV  [2POS-2p54mm]
J13  87832-1420  [14POS-2ROWS-2mm]
J14  53261-0471  [4POS-1p25mm]
J15  53261-0471  [4POS-1p25mm]
J16  53261-0471  [4POS-1p25mm]
R123  1k  [0603]
R124  1k  [0603]
R125  1k  [0603]
R126  1k  [0603]
R127  1k  [0603]
R128  4.7k  [0402]
R129  120  [0402]
R130  0  [0402]
R131  0  [0402]
R132  10k  [0402]
R133  120  [0402]
R134  10k  [0402]
R135  10k  [0402]
R136  4.7k  [0402]
R137  10k  [0402]
R138  33  [0603]
R139  1k  [0603]
R140  1k  [0603]
S_TP5  SMD_Testpoint  [5015pad]
S_TP6  SMD_Testpoint  [5015pad]
TP31  Testpoint  [24mil-plated]
sheet P18-Slave Vid DMD io
R143  10k  [0402]
TP32  Testpoint  [24mil-plated]
TP33  Testpoint  [24mil-plated]
sheet P19-Slave JTAG Osc Rst SSP
J17  TMMH-103-01-L-DV  [6POS-2ROWS-2mm]
R144  10k  [0402]
R145  1k  [0603]
R146  33  [0603]
R147  10k  [0402]
TP34  Testpoint  [24mil-plated]
TP35  Testpoint  [24mil-plated]
TP36  Testpoint  [24mil-plated]
TP37  Testpoint  [24mil-plated]
TP38  Testpoint  [24mil-plated]
TP39  Testpoint  [24mil-plated]
TP40  Testpoint  [24mil-plated]
TP41  Testpoint  [24mil-plated]
TP42  Testpoint  [24mil-plated]
TP43  Testpoint  [24mil-plated]
TP44  Testpoint  [24mil-plated]
TP45  Testpoint  [24mil-plated]
TP46  Testpoint  [24mil-plated]
TP47  Testpoint  [24mil-plated]
TP48  Testpoint  [24mil-plated]
sheet P20-Slave Ext Flash Intf
U22  DLPC900 (slave)  [516BGA]  (sections A,B,C,D,E,F,G,H,I,J)
sheet P21-Slave GPIOs
D8  LTST-C190EKT  [0603]
D9  LTST-C190GKT  [0603]
R158  4.7K  [0402]
R159  1K  [0603]
R160  10K  [0603]
R161  0  [0603]
R162  0  [0603]
R163  120  [0402]
R164  10K  [0402]
R165  120  [0402]
TP49  Testpoint  [24mil-plated]
TP50  Testpoint  [24mil-plated]
TP51  Testpoint  [24mil-plated]
TP52  Testpoint  [24mil-plated]
TP53  Testpoint  [24mil-plated]
TP54  Testpoint  [24mil-plated]
TP55  Testpoint  [24mil-plated]
TP56  Testpoint  [24mil-plated]
TP57  Testpoint  [24mil-plated]
TP58  Testpoint  [24mil-plated]
TP59  Testpoint  [24mil-plated]
TP60  Testpoint  [24mil-plated]
TP61  Testpoint  [24mil-plated]
TP62  Testpoint  [24mil-plated]
sheet P26-Inout Trigger, LED Driver
C349  0.1uF  [0402]
C350  0.1uF  [0402]
C351  0.1uF  [0402]
C352  0.1uF  [0402]
C353  0.1uF  [0402]
C354  0.1uF  [0402]
C355  0.1uF  [0402]
C356  0.1uF  [0402]
C357  0.1uF  [0402]
C358  0.1uF  [0402]
J22  TSM-103-01-T-SV  [3POS-2p54mm]
J23  0532610671  [6pos_1p25mm]
J24  TSM-103-01-T-SV  [3POS-2p54mm]
J25  TSM-103-01-T-SV  [3POS-2p54mm]
J26  S14B-PHDSS(LF)(SN)(P)  [HDR7X2]
J27  0532610671  [6pos_1p25mm]
J28  TSM-103-01-T-SV  [3POS-2p54mm]
R200  10k  [0402]
R201  10k  [0402]
R202  10k  [0402]
R203  10k  [0402]
R204  10k  [0402]
R205  10K  [0402]
R206  10k  [0402]
R207  10K  [0402]
S_TP15  SMD_Testpoint  [5015pad]
S_TP16  SMD_Testpoint  [5015pad]
S_TP17  SMD_Testpoint  [5015pad]
S_TP18  SMD_Testpoint  [5015pad]
U33  SN74AVC1T45DRLR  [SOT-563]
U34  SN74LVC1G17DBV  [DBV]
U35  SN74AVC1T45DRLR  [SOT-563]
U36  SN74LVC1G17DBV  [DBV]
U37  SN74AVC1T45DRLR  [SOT-563]
U38  SN74AVC1T45DRLR  [SOT-563]
sheet P27-Gen pwrgood posense clk
C359  0.1uF  [0402]
C360  1.0uF  [0402]
C361  0.1uF  [0402]
C362  DNI  [0402]
C363  0.1uF  [0402]
C364  0.1uF  [0402]
D12  LTST-C190GKT  [0603]
FB30  BLM18AG471SN1D  [0603]
FB31  BLM18AG471SN1D  [0603]
J29  TSM-102-01-T-SV  [2POS-2p54mm]
Q2  FDV303N  [SOT-23]
R208  4.7k  [0402]
R209  100  [0603]
R210  DNI  [0402]
R211  10k  [0402]
R212  1k  [0603]
R213  DNI  [0402]
R214  DNI  [0402]
R215  DNI  [0402]
R216  DNI  [0402]
R217  0  [0402]
R218  10k  [0402]
R219  0  [0402]
R220  0  [0402]
R221  0  [0402]
R222  0  [0402]
R223  0  [0402]
R224  0  [0402]
R225  10k  [0402]
R226  10k  [0402]
R227  10k  [0402]
R228  10k  [0402]
R229  10k  [0402]
R230  18  [0603]
R231  18  [0603]
R232  18  [0603]
S_TP19  SMD_Testpoint  [5015pad]
S_TP20  SMD_Testpoint  [5015pad]
S_TP21  SMD_Testpoint  [5015pad]
U39  TL7712ACDR  [8-SOIC]
U40  SN74LV21APWR  [14-TSSOP]
U41  DSC1101CI5-20.0000T  [6PINSxtal]
U42  CDCLVC1103PWR  [TSSOP-8]

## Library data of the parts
C126-C136 = CER_15PF_16V_5%_NP0_0402
R57 R72-R75 R83 R97 R105 R119 R128 R136 R158 R208 = 4.7K_OHM_1_10W_5%_0402
R58-R68 = 10.0_OHM_1_16W_1%_0402
TP13-TP62 = Testpoint
C137-C147 C361 C363 C364 = CER_0.1UF_16V_10%_X5R_0402
J6 J10 J12 J29 = TSM-102-01-T-SV_2POS_.1_SMD
J7 J17 = TMMH-103-01-L-DV_6POS_2ROWS_2MM
J8 = USB_RCPT_B-TYPE_R_A
R69 R77-R81 R120 R122 R138 R146 = 33_OHM_1_16W_5%_0402
R70 R71 R87-R90 R92-R96 R98-R104 R108 R113-R116 R121 R132 R134 R135 R137 R143 R144 R147 R164 R200-R207 R211 R213-R216 R218 R225-R229 = 10K_OHM_1_10W_5%_0402
R76 R123-R127 R139 R140 R145 R159 R212 = 1.0K_OHM_1_16W_5%_0402
R82 R160 = 10K_OHM_1_10W_5%_0603
R84 = 1.5K_OHM_1_10W_5%_0603
R85 R86 = 22.0_OHM_3_4W_1%_2010
U14 U19 = 74AHC1G125
U15 = SN65220_USB_PORT_TVS
R91 = 22_OHM_1_10W_1%_0402
U16-U18 = NOR_Flash_128Mbits_3.3V_56TSOP
J9 = CONN_HEADER_20POS_2.54mm
J11 J23 J27 = CONN_HEADER_6POS_1.25MM_R_A_SMD
R106 R107 R109-R112 R117 R118 R161 R162 = 0.0_OHM_1_10W_0603
SW1 = SWITCH_TACTILE_SPST-NO
U13 U22 = DLPC900_910_datasheet
U20 = TPS3838K33
U21 = 74LVC1G07_IC_BUFF_NON-INVERT
D6 D8 = LED_RED_CLEAR_0603
D7 D9 D12 = LED_GREEN_CLEAR_0603
J13 = 87832-1420_14POS_2ROWS_2MM_VERT
J14-J16 = Molex_CONN_HEADER_4POS_1.25MM_R
R129 R133 R163 R165 = 120_OHM_1_10W_5%_0402
R130 R131 R210 R217 R219-R224 = 0.0_OHM_1_10W_0402
S_TP5 S_TP6 S_TP15-S_TP21 = SMD_Testpoint
C349-C359 = CER_0.1UF_25V_10%_X5R_0402
J22 J24 J25 J28 = TSM-103-01-T-SV_3POS_.1_SMD
J26 = LED_CONN_HEADER_14POS_2MM
U33 U35 U37 U38 = SN74AVC1T45_level_translate
U34 U36 = SN74LVC1G17DBV_SCHMIT_TRIG
C360 = CER_1.0UF_16V_10%_X5R_0402
C362 = CER_56PF_50V_5%_NPO_0402
FB30 FB31 = FERRITE_CHIP_470_OHM_500MA_0603
Q2 = FDV303N_MOSFET_N
R209 = 100_OHM_1_10W_5%_0603
R230-R232 = 18_OHM_1_10W_5%_0603
U39 = TL7712A
U40 = SN74LV21A_DUAL_4-IN_AND_GATE
U41 = DSC1101_DSC1121
U42 = CDCLVC1103PWR

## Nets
GND: C126.2 C127.2 C128.2 C129.2 C130.2 C131.2 C132.2 C133.2 C134.2 C135.2 C136.2 C137.2 C138.2 C139.2 C140.2 C141.2 C142.2 C143.2 C144.2 C145.2 C146.2 C147.2 C349.2 C350.2 C351.2 C352.2 C353.2 C354.2 C355.2 C356.2 C357.2 C358.2 C359.2 C360.2 C361.2 C362.2 C363.2 C364.2 D6.1(CATHODE) D7.1(CATHODE) D8.1(CATHODE) D9.1(CATHODE) J6.2 J7.6 J8.4 J9.4 J9.6 J9.8 J9.10 J9.12 J9.14 J9.16 J9.18 J9.20 J10.2 J11.6 J11.7 J11.8 J12.2 J13.12 J13.13 J13.14 J14.4 J15.4 J16.4 J17.6 J23.3 J23.6 J23.7 J23.8 J26.12(P12) J26.13(P13) J26.14(P14) J27.3 J27.6 J27.7 J27.8 J29.2 Q2.S R71.2 R82.2 R87.2 R88.2 R103.2 R104.2 R119.2 R132.1 R134.2 R135.2 R137.2 R145.2 R147.2 R159.2 R160.2 R164.2 R201.2 R203.2 R205.2 R207.2 R211.2 SW1.3 SW1.4 U13.AC6(VPGM) U13.M25(HW_TEST_EN) U14.3(GND) U15.2(GND2) U15.5(GND5) U16.33(VSS) U16.52(VSS) U17.33(VSS) U17.52(VSS) U18.33(VSS) U18.52(VSS) U19.2(A) U19.3(GND) U20.1(CT) U20.2(GND) U21.1(NC) U21.3(GND) U22.AC6(VPGM) U22.M25(HW_TEST_EN) U33.2(GND) U34.3(GND) U35.2(GND) U36.3(GND) U37.2(GND) U38.2(GND) U39.4(GND) U40.7(GND) U41.3(GND) U42.4(GND) ; also on sheet 2 3 4 6 7 8 22 24 25 26 27 28
P12V: J26.1(P1) J26.2(P2) J26.3(P3) U39.2(\\~{RESI}N) U39.7(SENSE) U39.8(VCC) ; also on sheet 2 6 7
1P1V_SW_PWRGD: R217.1 ; also on sheet 2 6
1P8V_SW_PWRGD: R221.1 ; also on sheet 6
1P8VA_LDO_PG: R219.1 ; also on sheet 2
3P3V_SW_PWRGD: R223.1 ; also on sheet 6
AFE_ARSTZ: R57.2 U13.AC12(AFE_ARSTZ) ; also on sheet 4 22
ASIC_POSENSE: C362.1 R218.2 R220.1 R222.1 S_TP20.1 U40.6(1Y)
BLU_LED_EN: J26.7(P7) R134.1 U13.D24(BLU_LED_EN)
BLU_LED_PWM: J26.10(P10) U13.C20(BLU_LED_PWM)
BUTTON_RSTZ: J10.1 R105.2 SW1.1 SW1.2 U20.3(\~{_M}R)
CLKBUF_EN: R229.2 U42.2(1G)
CLKBUF_VIN: C363.1 FB31.1 R229.1 U42.6(VDD)
CLKBUFY0: R232.1 U42.3(Y0)
CLKBUFY1: R230.1 U42.8(Y1)
CLKBUFY2: R231.1 U42.5(Y2)
DADADDR0: R58.2 ; also on sheet 7
DADADDR1: R59.2 ; also on sheet 7
DADADDR2: R60.2 ; also on sheet 7
DADADDR3: R61.2 ; also on sheet 7
DADINTZ: R68.2 ; also on sheet 7
DADMODE0: R62.2 ; also on sheet 7
DADMODE1: R63.2 ; also on sheet 7
DADOEZ: R67.2 ; also on sheet 7
DADSEL0: R64.2 ; also on sheet 7
DADSEL1: R65.2 ; also on sheet 7
DADSTRB: R66.2 TP15.1 ; also on sheet 7
DASYNC: U13.R22(DA_SYNC_INPUT) U13.T23(FSD12_OUTPUT) U22.R22(DA_SYNC_INPUT)
EXT_TRIG1_IN_VCC: C350.1 C351.1 J22.2 J23.1 R200.1 U33.1(Vcca) U34.5(VCC)
EXT_TRIG1_OUT_VCC: C356.1 J25.2 J27.1 U37.6(Vccb)
EXT_TRIG2_IN_VCC: C353.1 C354.1 J23.4 J24.2 R202.1 U35.1(Vcca) U36.5(VCC)
EXT_TRIG2_OUT_VCC: C358.1 J27.4 J28.2 U38.6(Vccb)
F_OSC20M: R231.2 ; also on sheet 5
FORCE_SLAVE_RSTZ: J29.1 R225.2 U40.13(2D)
GRN_LED_EN: J26.6(P6) R135.1 U13.C25(GRN_LED_EN)
GRN_LED_PWM: J26.9(P9) U13.B20(GRN_LED_PWM)
HDMI_INTZ: U13.AB13(AFE_IRQ) ; also on sheet 22
HOLDBOOTZ: J12.1 R127.1 U13.F24(HOLD_BOOTZ) U22.F24(HOLD_BOOTZ)
M_3DLR_GPIO78: U13.AF9(RESERVED) ; also on sheet 4
M_CW_PWM: TP16.1 U13.AD8(RESERVED)
M_DADA0: C129.1 R58.1 U13.AB8(DADADDR_0)
M_DADA1: C128.1 R59.1 U13.AF4(DADADDR_1)
M_DADA2: C127.1 R60.1 U13.AE5(DADADDR_2)
M_DADA3: C126.1 R61.1 U13.AD6(DADADDR_3)
M_DADINTZ: C130.1 R68.1 U13.AC8(DAD_INTZ)
M_DADM0: C136.1 R62.1 U13.AE6(DADMODE_0)
M_DADM1: C135.1 R63.1 U13.AD7(DADMODE_1)
M_DADOEZ: C131.1 R67.1 U13.AE7(DADOEZ)
M_DADSEL0: C134.1 R64.1 U13.AC7(DADSEL_0)
M_DADSEL1: C133.1 R65.1 U13.AE4(DADSEL_1)
M_DADSTB: C132.1 R66.1 U13.AF5(DADSTRB)
M_DCLKA_N: U13.J4(DCKB_N) ; also on sheet 7
M_DCLKA_P: U13.J3(DCKB_P) ; also on sheet 7
M_DCLKB_N: U13.V3(DCKA_N) ; also on sheet 7
M_DCLKB_P: U13.V4(DCKA_P) ; also on sheet 7
M_DDA00_N: U13.N2(DDB_N_15) ; also on sheet 7
M_DDA00_P: U13.N1(DDB_P_15) ; also on sheet 7
M_DDA01_N: U13.N4(DDB_N_14) ; also on sheet 7
M_DDA01_P: U13.N3(DDB_P_14) ; also on sheet 7
M_DDA02_N: U13.M1(DDB_N_13) ; also on sheet 7
M_DDA02_P: U13.M2(DDB_P_13) ; also on sheet 7
M_DDA03_N: U13.M4(DDB_N_12) ; also on sheet 7
M_DDA03_P: U13.M3(DDB_P_12) ; also on sheet 7
M_DDA04_N: U13.L2(DDB_N_11) ; also on sheet 7
M_DDA04_P: U13.L1(DDB_P_11) ; also on sheet 7
M_DDA05_N: U13.L4(DDB_N_10) ; also on sheet 7
M_DDA05_P: U13.L3(DDB_P_10) ; also on sheet 7
M_DDA06_N: U13.K2(DDB_N_9) ; also on sheet 7
M_DDA06_P: U13.K1(DDB_P_9) ; also on sheet 7
M_DDA07_N: U13.K4(DDB_N_8) ; also on sheet 7
M_DDA07_P: U13.K3(DDB_P_8) ; also on sheet 7
M_DDA08_N: U13.H2(DDB_N_7) ; also on sheet 7
M_DDA08_P: U13.H1(DDB_P_7) ; also on sheet 7
M_DDA09_N: U13.H4(DDB_N_6) ; also on sheet 7
M_DDA09_P: U13.H3(DDB_P_6) ; also on sheet 7
M_DDA10_N: U13.G2(DDB_N_5) ; also on sheet 7
M_DDA10_P: U13.G1(DDB_P_5) ; also on sheet 7
M_DDA11_N: U13.G4(DDB_N_4) ; also on sheet 7
M_DDA11_P: U13.G3(DDB_P_4) ; also on sheet 7
M_DDA12_N: U13.F2(DDB_N_3) ; also on sheet 7
M_DDA12_P: U13.F1(DDB_P_3) ; also on sheet 7
M_DDA13_N: U13.F4(DDB_N_2) ; also on sheet 7
M_DDA13_P: U13.F3(DDB_P_2) ; also on sheet 7
M_DDA14_N: U13.E2(DDB_N_1) ; also on sheet 7
M_DDA14_P: U13.E1(DDB_P_1) ; also on sheet 7
M_DDA15_N: U13.D2(DDB_N_0) ; also on sheet 7
M_DDA15_P: U13.D1(DDB_P_0) ; also on sheet 7
M_DDB00_N: U13.P3(DDA_N_15) ; also on sheet 7
M_DDB00_P: U13.P4(DDA_P_15) ; also on sheet 7
M_DDB01_N: U13.P1(DDA_N_14) ; also on sheet 7
M_DDB01_P: U13.P2(DDA_P_14) ; also on sheet 7
M_DDB02_N: U13.R3(DDA_N_13) ; also on sheet 7
M_DDB02_P: U13.R4(DDA_P_13) ; also on sheet 7
M_DDB03_N: U13.R1(DDA_N_12) ; also on sheet 7
M_DDB03_P: U13.R2(DDA_P_12) ; also on sheet 7
M_DDB04_N: U13.T3(DDA_N_11) ; also on sheet 7
M_DDB04_P: U13.T4(DDA_P_11) ; also on sheet 7
M_DDB05_N: U13.T1(DDA_N_10) ; also on sheet 7
M_DDB05_P: U13.T2(DDA_P_10) ; also on sheet 7
M_DDB06_N: U13.U3(DDA_N_9) ; also on sheet 7
M_DDB06_P: U13.U4(DDA_P_9) ; also on sheet 7
M_DDB07_N: U13.U1(DDA_N_8) ; also on sheet 7
M_DDB07_P: U13.U2(DDA_P_8) ; also on sheet 7
M_DDB08_N: U13.W3(DDA_N_7) ; also on sheet 7
M_DDB08_P: U13.W4(DDA_P_7) ; also on sheet 7
M_DDB09_N: U13.W1(DDA_N_6) ; also on sheet 7
M_DDB09_P: U13.W2(DDA_P_6) ; also on sheet 7
M_DDB10_N: U13.Y1(DDA_N_5) ; also on sheet 7
M_DDB10_P: U13.Y2(DDA_P_5) ; also on sheet 7
M_DDB11_N: U13.Y3(DDA_N_4) ; also on sheet 7
M_DDB11_P: U13.Y4(DDA_P_4) ; also on sheet 7
M_DDB12_N: U13.AA1(DDA_N_3) ; also on sheet 7
M_DDB12_P: U13.AA2(DDA_P_3) ; also on sheet 7
M_DDB13_N: U13.AA3(DDA_N_2) ; also on sheet 7
M_DDB13_P: U13.AA4(DDA_P_2) ; also on sheet 7
M_DDB14_N: U13.AB1(DDA_N_1) ; also on sheet 7
M_DDB14_P: U13.AB2(DDA_P_1) ; also on sheet 7
M_DDB15_N: U13.AC1(DDA_N_0) ; also on sheet 7
M_DDB15_P: U13.AC2(DDA_P_0) ; also on sheet 7
M_EXT_RSTZ: R72.1 U13.T24(EXT_RSTZ) ; also on sheet 7
M_FLASH0_WP#: R89.2 U17.16(WP#/ACC)
M_FLASH1_WP#: R90.2 U16.16(WP#/ACC)
M_FLASH2_WP#: R96.2 U18.16(WP#/ACC)
M_GPIO8_PWM: J13.3 U13.A21(GPIO_PWM_0)
M_GPIO9_PWM: J13.5 U13.B21(GPIO_PWM_1)
M_GPIO10_PWM: J13.7 U13.A22(GPIO_PWM_2)
M_GPIO11_PWM: J13.9 U13.A23(GPIO_PWM_3)
M_GPIO23_AUX2: J13.11 U13.E21(GPIO_8)
M_GPIO43: J13.4 U13.U25(GPIO_4)
M_GPIO44: J13.6 U13.U24(GPIO_5)
M_GPIO49: J13.8 U13.V24(GPIO_6)
M_GPIO50: J13.10 U13.V23(GPIO_7)
M_GPIO66: R136.1 R138.1 U13.J23(TEST_FUNC_1)
M_GPIO67: U13.J24(TEST_FUNC_2) ; also on sheet 5
M_GPIO68: U13.J25(TEST_FUNC_3) ; also on sheet 5
M_GPIO69: U13.J26(TEST_FUNC_4) ; also on sheet 5
M_GPIO70: U13.K22(TEST_FUNC_5) ; also on sheet 5
M_IIC_BUSY: TP31.1 U13.G24(RESERVED)
M_OCLKA_PIN: R69.1 U13.AF6(OCLKA)
M_OSC20M: R232.2 U13.M26(MOSCP)
M_P1A0: U13.AE12(P1_A0) ; also on sheet 4
M_P1A1: U13.AF12(P1_A1) ; also on sheet 4
M_P1A2: U13.AF13(P1_A2) ; also on sheet 4
M_P1A3: U13.AF14(P1_A3) ; also on sheet 4
M_P1A4: U13.AC13(P1_A4) ; also on sheet 4
M_P1A5: U13.AD13(P1_A5) ; also on sheet 4
M_P1A6: U13.AE13(P1_A6) ; also on sheet 4
M_P1A7: U13.AE14(P1_A7) ; also on sheet 4
M_P1A8: U13.AE15(P1_A8) ; also on sheet 4
M_P1A9: U13.AD15(P1_A9) ; also on sheet 4
M_P1B0: U13.AD14(P1_B0) ; also on sheet 4
M_P1B1: U13.AC14(P1_B1) ; also on sheet 4
M_P1B2: U13.AF15(P1_B2) ; also on sheet 4
M_P1B3: U13.AF16(P1_B3) ; also on sheet 4
M_P1B4: U13.AE16(P1_B4) ; also on sheet 4
M_P1B5: U13.AD16(P1_B5) ; also on sheet 4
M_P1B6: U13.AC16(P1_B6) ; also on sheet 4
M_P1B7: U13.AC15(P1_B7) ; also on sheet 4
M_P1B8: U13.AB18(P1_B8) ; also on sheet 4
M_P1B9: U13.AF18(P1_B9) ; also on sheet 4
M_P1C0: U13.AE18(P1_C0) ; also on sheet 4
M_P1C1: U13.AC19(P1_C1) ; also on sheet 4
M_P1C2: U13.AF20(P1_C2) ; also on sheet 4
M_P1C3: U13.AF19(P1_C3) ; also on sheet 4
M_P1C4: U13.AE19(P1_C4) ; also on sheet 4
M_P1C5: U13.AD19(P1_C5) ; also on sheet 4
M_P1C6: U13.AF21(P1_C6) ; also on sheet 4
M_P1C7: U13.AE21(P1_C7) ; also on sheet 4
M_P1C8: U13.AE20(P1_C8) ; also on sheet 4
M_P1C9: U13.AD20(P1_C9) ; also on sheet 4
M_P1DATEN: TP13.1 U13.AF22(P_DATAEN1) ; also on sheet 4
M_P1HS: U13.AD21(P1_HSYNC) ; also on sheet 4
M_P1VS: TP14.1 U13.AC20(P1_VSYNC) ; also on sheet 4
M_P2A0: U13.AB19(P2_A0) ; also on sheet 4
M_P2A1: U13.AE23(P2_A1) ; also on sheet 4
M_P2A2: U13.AD22(P2_A2) ; also on sheet 4
M_P2A3: U13.AC21(P2_A3) ; also on sheet 4
M_P2A4: U13.AB20(P2_A4) ; also on sheet 4
M_P2A5: U13.AD23(P2_A5) ; also on sheet 4
M_P2A6: U13.AC22(P2_A6) ; also on sheet 4
M_P2A7: U13.AB21(P2_A7) ; also on sheet 4
M_P2A8: U13.AD25(P2_A8) ; also on sheet 4
M_P2A9: U13.AD26(P2_A9) ; also on sheet 4
M_P2B0: U13.AC24(P2_B0) ; also on sheet 4
M_P2B1: U13.AC25(P2_B1) ; also on sheet 4
M_P2B2: U13.AB23(P2_B2) ; also on sheet 4
M_P2B3: U13.AC26(P2_B3) ; also on sheet 4
M_P2B4: U13.AB24(P2_B4) ; also on sheet 4
M_P2B5: U13.AA22(P2_B5) ; also on sheet 4
M_P2B6: U13.AB25(P2_B6) ; also on sheet 4
M_P2B7: U13.AA23(P2_B7) ; also on sheet 4
M_P2B8: U13.AB26(P2_B8) ; also on sheet 4
M_P2B9: U13.Y22(P2_B9) ; also on sheet 4
M_P2C0: U13.AA24(P2_C0) ; also on sheet 4
M_P2C1: U13.AA25(P2_C1) ; also on sheet 4
M_P2C2: U13.AA26(P2_C2) ; also on sheet 4
M_P2C3: U13.W22(P2_C3) ; also on sheet 4
M_P2C4: U13.Y23(P2_C4) ; also on sheet 4
M_P2C5: U13.Y24(P2_C5) ; also on sheet 4
M_P2C6: U13.Y25(P2_C6) ; also on sheet 4
M_P2C7: U13.Y26(P2_C7) ; also on sheet 4
M_P2C8: U13.V22(P2_C8) ; also on sheet 4
M_P2C9: U13.W23(P2_C9) ; also on sheet 4
M_PCLK1: U13.AE22(P_CLK1) ; also on sheet 4
M_PIPESTAT0: TP28.1 U13.C6(RESERVED)
M_PIPESTAT1: TP27.1 U13.B5(RESERVED)
M_PIPESTAT2: TP26.1 U13.A4(RESERVED)
M_PM_CSZ0: R94.2 U13.D13(PM_CSZ_0) U17.32(CE#)
M_PM_CSZ1: R93.2 U13.E12(PM_CSZ_1) U16.32(CE#)
M_PM_CSZ2: R92.2 U13.A13(PM_CSZ_2) U18.32(CE#)
M_PM_OEZ: U13.C13(PM_OEZ) U16.34(OE#) U17.34(OE#) U18.34(OE#)
M_PM_WEZ: R91.1 U16.13(WE#) U17.13(WE#) U18.13(WE#)
M_PMADDR00: U13.C7(PM_ADDR_00) U16.31(A0) U17.31(A0) U18.31(A0)
M_PMADDR01: U13.A7(PM_ADDR_01) U16.26(A1) U17.26(A1) U18.26(A1)
M_PMADDR02: U13.B7(PM_ADDR_02) U16.25(A2) U17.25(A2) U18.25(A2)
M_PMADDR03: U13.C8(PM_ADDR_03) U16.24(A3) U17.24(A3) U18.24(A3)
M_PMADDR04: U13.D8(PM_ADDR_04) U16.23(A4) U17.23(A4) U18.23(A4)
M_PMADDR05: U13.A8(PM_ADDR_05) U16.22(A5) U17.22(A5) U18.22(A5)
M_PMADDR06: U13.B8(PM_ADDR_06) U16.21(A6) U17.21(A6) U18.21(A6)
M_PMADDR07: U13.C9(PM_ADDR_07) U16.20(A7) U17.20(A7) U18.20(A7)
M_PMADDR08: U13.D9(PM_ADDR_08) U16.10(A8) U17.10(A8) U18.10(A8)
M_PMADDR09: U13.E9(PM_ADDR_09) U16.9(A9) U17.9(A9) U18.9(A9)
M_PMADDR10: U13.A9(PM_ADDR_10) U16.8(A10) U17.8(A10) U18.8(A10)
M_PMADDR11: U13.B9(PM_ADDR_11) U16.7(A11) U17.7(A11) U18.7(A11)
M_PMADDR12: U13.C10(PM_ADDR_12) U16.6(A12) U17.6(A12) U18.6(A12)
M_PMADDR13: U13.D10(PM_ADDR_13) U16.5(A13) U17.5(A13) U18.5(A13)
M_PMADDR14: U13.E10(PM_ADDR_14) U16.4(A14) U17.4(A14) U18.4(A14)
M_PMADDR15: U13.C11(PM_ADDR_15) U16.3(A15) U17.3(A15) U18.3(A15)
M_PMADDR16: U13.D11(PM_ADDR_16) U16.54(A16) U17.54(A16) U18.54(A16)
M_PMADDR17: U13.A11(PM_ADDR_17) U16.19(A17) U17.19(A17) U18.19(A17)
M_PMADDR18: U13.B11(PM_ADDR_18) U16.18(A18) U17.18(A18) U18.18(A18)
M_PMADDR19: U13.C12(PM_ADDR_19) U16.11(A19) U17.11(A19) U18.11(A19)
M_PMADDR20: U13.D12(PM_ADDR_20) U16.12(A20) U17.12(A20) U18.12(A20)
M_PMADDR21_GPIO35: R88.1 U13.E11(PM_ADDR_21) U16.15(A21) U17.15(A21) U18.15(A21)
M_PMADDR22_GPIO36: R87.1 U13.A12(PM_ADDR_22) U16.2(A22) U17.2(A22) U18.2(A22)
M_PMDATA_00: U13.B13(PM_DATA_00) U16.35(DQ0) U17.35(DQ0) U18.35(DQ0)
M_PMDATA_01: U13.C14(PM_DATA_01) U16.37(DQ1) U17.37(DQ1) U18.37(DQ1)
M_PMDATA_02: U13.D14(PM_DATA_02) U16.39(DQ2) U17.39(DQ2) U18.39(DQ2)
M_PMDATA_03: U13.E13(PM_DATA_03) U16.41(DQ3) U17.41(DQ3) U18.41(DQ3)
M_PMDATA_04: U13.A14(PM_DATA_04) U16.44(DQ4) U17.44(DQ4) U18.44(DQ4)
M_PMDATA_05: U13.B14(PM_DATA_05) U16.46(DQ5) U17.46(DQ5) U18.46(DQ5)
M_PMDATA_06: U13.C15(PM_DATA_06) U16.48(DQ6) U17.48(DQ6) U18.48(DQ6)
M_PMDATA_07: U13.D15(PM_DATA_07) U16.50(DQ7) U17.50(DQ7) U18.50(DQ7)
M_PMDATA_08: U13.E14(PM_DATA_08) U16.36(DQ8) U17.36(DQ8) U18.36(DQ8)
M_PMDATA_09: U13.C16(PM_DATA_09) U16.38(DQ9) U17.38(DQ9) U18.38(DQ9)
M_PMDATA_10: U13.D16(PM_DATA_10) U16.40(DQ10) U17.40(DQ10) U18.40(DQ10)
M_PMDATA_11: U13.B15(PM_DATA_11) U16.42(DQ11) U17.42(DQ11) U18.42(DQ11)
M_PMDATA_12: U13.A15(PM_DATA_12) U16.45(DQ12) U17.45(DQ12) U18.45(DQ12)
M_PMDATA_13: U13.A16(PM_DATA_13) U16.47(DQ13) U17.47(DQ13) U18.47(DQ13)
M_PMDATA_14: U13.B16(PM_DATA_14) U16.49(DQ14) U17.49(DQ14) U18.49(DQ14)
M_PMDATA_15: U13.C17(PM_DATA_15) U16.51(DQ15) U17.51(DQ15) U18.51(DQ15)
M_PMDINTZ: R70.2 U13.AE8(RESERVED)
M_PMWEZ_PIN: R91.2 U13.B12(PM_WEZ)
M_POSENSE: R220.2 U13.P22(POSENSE) U16.14(RESET#) U17.14(RESET#) U18.14(RESET#)
M_RTCK: R106.1 R120.2
M_RTCK_PIN: R120.1 U13.E4(RTCK)
M_SCL0: J14.1 R124.2 U13.A10(I2C0_SCL)
M_SCL1: J15.1 R126.2 U13.D20(I2C1_SCL) U22.A10(I2C0_SCL) ; also on sheet 22 28
M_SCL2: J16.1 R139.2 U13.B22(I2C2_SCL)
M_SCTLA_N: U13.J2(SCB_N) ; also on sheet 7
M_SCTLA_P: U13.J1(SCB_P) ; also on sheet 7
M_SCTLB_N: U13.V1(SCA_N) ; also on sheet 7
M_SCTLB_P: U13.V2(SCA_P) ; also on sheet 7
M_SDA0: J14.2 R123.2 U13.B10(I2C0_SDA)
M_SDA1: J15.2 R125.2 U13.E19(I2C1_SDA) U22.B10(I2C0_SDA) ; also on sheet 22 28
M_SDA2: J16.2 R140.2 U13.C21(I2C2_SDA)
M_SEQ_AUX6: R130.1 U13.E26(SEQ_AUX6)
M_SEQ_AUX7: R131.1 U13.F26(SEQ_AUX7)
M_SEQ_INT1: R131.2 S_TP6.1 U13.G26(SEQ_INT1)
M_SEQ_INT2: R130.2 S_TP5.1 U13.H26(SEQ_INT2)
M_SEQSYNC_PIN: R122.1 U13.AB9(SEQ_SYNC)
M_SSP0_CLK: R77.1 U13.AD4(SSP0_CLK)
M_SSP0_CSZ0: R73.2 R81.1 U13.AC5(SSP0_CSZ_0)
M_SSP0_CSZ1: R74.2 R80.1 U13.AB6(SSP0_CSZ_1)
M_SSP0_CSZ2: R75.2 R79.1 U13.AC3(SSP0_CSZ_2)
M_SSP0_TXD: R78.1 U13.AB7(SSP0_TXD)
M_STATUS_GRN: R133.1 U13.AB12(HEARTBEAT)
M_STATUS_RED: R129.1 U13.AC11(FAULT_STATUS)
M_TDO1: R111.1 R118.2 U13.N23(TDO1)
M_TDO2: R109.1 R117.1 U13.N22(TDO2)
M_TRACECLK: TP30.1 U13.D7(RESERVED)
M_TRACESYNC: TP29.1 U13.A5(RESERVED)
M_TSTPT0: R116.2 TP25.1 U13.C2(RESERVED)
M_TSTPT1: R115.2 TP24.1 U13.D3(RESERVED)
M_TSTPT2: R114.2 TP23.1 U13.E6(RESERVED)
M_TSTPT3: R113.2 TP22.1 U13.D5(RESERVED)
M_TSTPT4: TP21.1 U13.E7(RESERVED)
M_TSTPT5: TP20.1 U13.C4(RESERVED)
M_TSTPT6: TP19.1 U13.B4(RESERVED)
M_TSTPT7: TP18.1 U13.E8(RESERVED)
M_UART0_CTSZ: J7.4 R71.1 U13.AE2(UART0_CTSZ)
M_UART0_RTSZ: J7.5 U13.AD2(UART0_RTSZ)
M_UART0_RXD: J7.3 U13.AD1(UART0_RXD)
M_UART0_TXD: J7.2 U13.AB3(UART0_TXD)
M_USB_ENZ: R83.1 U13.E25(USB_ENZ) U14.1(~{OE})
M_USB_N: R85.2 U13.C5(USB_DAT_N)
M_USB_P: R86.2 U13.D6(USB_DAT_P)
MASTER_ASIC: R128.1 U13.V26(CTRL_MODE_CFG)
MFLASH_RYBYZ: R95.2 U16.17(RY/BY#) U17.17(RY/BY#) U18.17(RY/BY#)
OCLKA: J6.1 R69.2
OSC20: U41.4(OUT) U42.1(CLK_IN)
OSC_EN: R228.2 U41.1(EN)
OSC_PWR: C364.1 FB30.2 R228.1 U41.6(VDD)
P1P8V: J22.3 J24.3 J25.3 J28.3 ; also on sheet 6 24 26 27
P3P3V: C137.1 C138.1 C139.1 C140.1 C141.1 C142.1 C143.1 C144.1 C145.1 C146.1 C147.1 C349.1 C352.1 C355.1 C357.1 C361.1 FB30.1 FB31.2 J7.1 J9.1 J9.2 J13.1 J13.2 J14.3 J15.3 J16.3 J17.1 J22.1 J24.1 J25.1 J26.11(P11) J28.1 R57.1 R70.1 R72.2 R73.1 R74.1 R75.1 R76.1 R83.2 R89.1 R90.1 R92.1 R93.1 R94.1 R95.1 R96.1 R97.1 R98.1 R99.1 R100.1 R101.1 R102.1 R105.1 R108.1 R113.1 R114.1 R115.1 R116.1 R121.1 R123.1 R124.1 R125.1 R126.1 R127.2 R128.2 R136.2 R139.1 R140.1 R143.1 R144.1 R158.2 R204.1 R206.1 R208.1 R209.1 R213.1 R214.1 R215.1 R216.1 R218.1 R225.1 R226.1 R227.1 U14.5(VCC) U16.29(VIO) U16.43(VCC) U17.29(VIO) U17.43(VCC) U18.29(VIO) U18.43(VCC) U19.5(VCC) U20.5(VDD) U21.5(VCC) U33.6(Vccb) U35.6(Vccb) U37.1(Vcca) U38.1(Vcca) U40.14(VCC) ; also on sheet 2 3 6 7 8 22 24 26 27 28
PG12V_CT: C360.1 U39.3(CT)
PG12V_REF: C359.1 U39.1(REF)
PG12V_RST: R211.1 U39.6(RESET)
POS_1A_IN: R213.2 R219.2 U40.1(1A)
POS_1B_IN: R214.2 R217.2 U40.2(1B)
POS_1C_IN: R215.2 R221.2 U40.4(1C)
POS_1D_IN: R216.2 R223.2 U40.5(1D)
POWERGOOD: R208.2 R210.1 R212.1 S_TP19.1 U13.T26(PWRGOOD) U21.4(Y) U39.5(\\~{RESE}T) U40.9(2A)
RED_LED_EN: J26.5(P5) R132.2 U13.B26(RED_LED_EN)
RED_LED_PWM: J26.8(P8) U13.B19(RED_LED_PWM)
RTCK: J9.11 R100.2 R106.2 R107.2
S_3DLR_GPIO78: U22.AF9(RESERVED) ; also on sheet 4
S_CW_PWM: TP34.1 U22.AD8(RESERVED)
S_DADINTZ: R143.2 U22.AC8(DAD_INTZ)
S_DCLKA_N: U22.J4(DCKB_N) ; also on sheet 7
S_DCLKA_P: U22.J3(DCKB_P) ; also on sheet 7
S_DCLKB_N: U22.V3(DCKA_N) ; also on sheet 7
S_DCLKB_P: U22.V4(DCKA_P) ; also on sheet 7
S_DDA00_N: U22.N2(DDB_N_15) ; also on sheet 7
S_DDA00_P: U22.N1(DDB_P_15) ; also on sheet 7
S_DDA01_N: U22.N4(DDB_N_14) ; also on sheet 7
S_DDA01_P: U22.N3(DDB_P_14) ; also on sheet 7
S_DDA02_N: U22.M1(DDB_N_13) ; also on sheet 7
S_DDA02_P: U22.M2(DDB_P_13) ; also on sheet 7
S_DDA03_N: U22.M4(DDB_N_12) ; also on sheet 7
S_DDA03_P: U22.M3(DDB_P_12) ; also on sheet 7
S_DDA04_N: U22.L2(DDB_N_11) ; also on sheet 7
S_DDA04_P: U22.L1(DDB_P_11) ; also on sheet 7
S_DDA05_N: U22.L4(DDB_N_10) ; also on sheet 7
S_DDA05_P: U22.L3(DDB_P_10) ; also on sheet 7
S_DDA06_N: U22.K2(DDB_N_9) ; also on sheet 7
S_DDA06_P: U22.K1(DDB_P_9) ; also on sheet 7
S_DDA07_N: U22.K4(DDB_N_8) ; also on sheet 7
S_DDA07_P: U22.K3(DDB_P_8) ; also on sheet 7
S_DDA08_N: U22.H2(DDB_N_7) ; also on sheet 7
S_DDA08_P: U22.H1(DDB_P_7) ; also on sheet 7
S_DDA09_N: U22.H4(DDB_N_6) ; also on sheet 7
S_DDA09_P: U22.H3(DDB_P_6) ; also on sheet 7
S_DDA10_N: U22.G2(DDB_N_5) ; also on sheet 7
S_DDA10_P: U22.G1(DDB_P_5) ; also on sheet 7
S_DDA11_N: U22.G4(DDB_N_4) ; also on sheet 7
S_DDA11_P: U22.G3(DDB_P_4) ; also on sheet 7
S_DDA12_N: U22.F2(DDB_N_3) ; also on sheet 7
S_DDA12_P: U22.F1(DDB_P_3) ; also on sheet 7
S_DDA13_N: U22.F4(DDB_N_2) ; also on sheet 7
S_DDA13_P: U22.F3(DDB_P_2) ; also on sheet 7
S_DDA14_N: U22.E2(DDB_N_1) ; also on sheet 7
S_DDA14_P: U22.E1(DDB_P_1) ; also on sheet 7
S_DDA15_N: U22.D2(DDB_N_0) ; also on sheet 7
S_DDA15_P: U22.D1(DDB_P_0) ; also on sheet 7
S_DDB00_N: U22.P3(DDA_N_15) ; also on sheet 7
S_DDB00_P: U22.P4(DDA_P_15) ; also on sheet 7
S_DDB01_N: U22.P1(DDA_N_14) ; also on sheet 7
S_DDB01_P: U22.P2(DDA_P_14) ; also on sheet 7
S_DDB02_N: U22.R3(DDA_N_13) ; also on sheet 7
S_DDB02_P: U22.R4(DDA_P_13) ; also on sheet 7
S_DDB03_N: U22.R1(DDA_N_12) ; also on sheet 7
S_DDB03_P: U22.R2(DDA_P_12) ; also on sheet 7
S_DDB04_N: U22.T3(DDA_N_11) ; also on sheet 7
S_DDB04_P: U22.T4(DDA_P_11) ; also on sheet 7
S_DDB05_N: U22.T1(DDA_N_10) ; also on sheet 7
S_DDB05_P: U22.T2(DDA_P_10) ; also on sheet 7
S_DDB06_N: U22.U3(DDA_N_9) ; also on sheet 7
S_DDB06_P: U22.U4(DDA_P_9) ; also on sheet 7
S_DDB07_N: U22.U1(DDA_N_8) ; also on sheet 7
S_DDB07_P: U22.U2(DDA_P_8) ; also on sheet 7
S_DDB08_N: U22.W3(DDA_N_7) ; also on sheet 7
S_DDB08_P: U22.W4(DDA_P_7) ; also on sheet 7
S_DDB09_N: U22.W1(DDA_N_6) ; also on sheet 7
S_DDB09_P: U22.W2(DDA_P_6) ; also on sheet 7
S_DDB10_N: U22.Y1(DDA_N_5) ; also on sheet 7
S_DDB10_P: U22.Y2(DDA_P_5) ; also on sheet 7
S_DDB11_N: U22.Y3(DDA_N_4) ; also on sheet 7
S_DDB11_P: U22.Y4(DDA_P_4) ; also on sheet 7
S_DDB12_N: U22.AA1(DDA_N_3) ; also on sheet 7
S_DDB12_P: U22.AA2(DDA_P_3) ; also on sheet 7
S_DDB13_N: U22.AA3(DDA_N_2) ; also on sheet 7
S_DDB13_P: U22.AA4(DDA_P_2) ; also on sheet 7
S_DDB14_N: U22.AB1(DDA_N_1) ; also on sheet 7
S_DDB14_P: U22.AB2(DDA_P_1) ; also on sheet 7
S_DDB15_N: U22.AC1(DDA_N_0) ; also on sheet 7
S_DDB15_P: U22.AC2(DDA_P_0) ; also on sheet 7
S_EXTRSTZ: TP35.1 U22.T24(EXT_RSTZ)
S_FSD12: TP52.1 U22.T23(FSD12_OUTPUT)
S_GPIO04: TP60.1 U22.B19(RED_LED_PWM)
S_GPIO05: TP49.1 U22.B20(GRN_LED_PWM)
S_GPIO06: TP50.1 U22.C20(BLU_LED_PWM)
S_GPIO21_AUX0: TP51.1 U22.E20(TRIG_OUT_1)
S_GPIO22_AUX1: TP53.1 U22.D22(TRIG_OUT_2)
S_GPIO23_AUX2: TP54.1 U22.E21(GPIO_8)
S_GPIO43: TP55.1 U22.U25(GPIO_4)
S_GPIO44: TP56.1 U22.U24(GPIO_5)
S_GPIO49: TP58.1 U22.V24(GPIO_6)
S_GPIO50: TP59.1 U22.V23(GPIO_7)
S_I2C_BUSY: TP57.1 U22.G24(RESERVED)
S_ICTSEN: R145.1 U22.M24(ICTSEN)
S_LMPSTAT: R164.1 U22.AF8(RESERVED)
S_OSC20M: R230.2 U22.M26(MOSCP)
S_P1A0: U22.AE12(P1_A0) ; also on sheet 4
S_P1A1: U22.AF12(P1_A1) ; also on sheet 4
S_P1A2: U22.AF13(P1_A2) ; also on sheet 4
S_P1A3: U22.AF14(P1_A3) ; also on sheet 4
S_P1A4: U22.AC13(P1_A4) ; also on sheet 4
S_P1A5: U22.AD13(P1_A5) ; also on sheet 4
S_P1A6: U22.AE13(P1_A6) ; also on sheet 4
S_P1A7: U22.AE14(P1_A7) ; also on sheet 4
S_P1A8: U22.AE15(P1_A8) ; also on sheet 4
S_P1A9: U22.AD15(P1_A9) ; also on sheet 4
S_P1B0: U22.AD14(P1_B0) ; also on sheet 4
S_P1B1: U22.AC14(P1_B1) ; also on sheet 4
S_P1B2: U22.AF15(P1_B2) ; also on sheet 4
S_P1B3: U22.AF16(P1_B3) ; also on sheet 4
S_P1B4: U22.AE16(P1_B4) ; also on sheet 4
S_P1B5: U22.AD16(P1_B5) ; also on sheet 4
S_P1B6: U22.AC16(P1_B6) ; also on sheet 4
S_P1B7: U22.AC15(P1_B7) ; also on sheet 4
S_P1B8: U22.AB18(P1_B8) ; also on sheet 4
S_P1B9: U22.AF18(P1_B9) ; also on sheet 4
S_P1C0: U22.AE18(P1_C0) ; also on sheet 4
S_P1C1: U22.AC19(P1_C1) ; also on sheet 4
S_P1C2: U22.AF20(P1_C2) ; also on sheet 4
S_P1C3: U22.AF19(P1_C3) ; also on sheet 4
S_P1C4: U22.AE19(P1_C4) ; also on sheet 4
S_P1C5: U22.AD19(P1_C5) ; also on sheet 4
S_P1C6: U22.AF21(P1_C6) ; also on sheet 4
S_P1C7: U22.AE21(P1_C7) ; also on sheet 4
S_P1C8: U22.AE20(P1_C8) ; also on sheet 4
S_P1C9: U22.AD20(P1_C9) ; also on sheet 4
S_P1DATEN: TP32.1 U22.AF22(P_DATAEN1) ; also on sheet 4
S_P1HS: U22.AD21(P1_HSYNC) ; also on sheet 4
S_P1VS: TP33.1 U22.AC20(P1_VSYNC) ; also on sheet 4
S_P2A0: U22.AB19(P2_A0) ; also on sheet 4
S_P2A1: U22.AE23(P2_A1) ; also on sheet 4
S_P2A2: U22.AD22(P2_A2) ; also on sheet 5
S_P2A3: U22.AC21(P2_A3) ; also on sheet 5
S_P2A4: U22.AB20(P2_A4) ; also on sheet 5
S_P2A5: U22.AD23(P2_A5) ; also on sheet 5
S_P2A6: U22.AC22(P2_A6) ; also on sheet 5
S_P2A7: U22.AB21(P2_A7) ; also on sheet 5
S_P2A8: U22.AD25(P2_A8) ; also on sheet 5
S_P2A9: U22.AD26(P2_A9) ; also on sheet 5
S_P2B0: U22.AC24(P2_B0) ; also on sheet 5
S_P2B1: U22.AC25(P2_B1) ; also on sheet 5
S_P2B2: U22.AB23(P2_B2) ; also on sheet 5
S_P2B3: U22.AC26(P2_B3) ; also on sheet 5
S_P2B4: U22.AB24(P2_B4) ; also on sheet 5
S_P2B5: U22.AA22(P2_B5) ; also on sheet 5
S_P2B6: U22.AB25(P2_B6) ; also on sheet 5
S_P2B7: U22.AA23(P2_B7) ; also on sheet 5
S_P2B8: U22.AB26(P2_B8) ; also on sheet 5
S_P2B9: U22.Y22(P2_B9) ; also on sheet 5
S_P2C0: U22.AA24(P2_C0) ; also on sheet 5
S_P2C1: U22.AA25(P2_C1) ; also on sheet 5
S_P2C2: U22.AA26(P2_C2) ; also on sheet 5
S_P2C3: U22.W22(P2_C3) ; also on sheet 5
S_P2C4: U22.Y23(P2_C4) ; also on sheet 5
S_P2C5: U22.Y24(P2_C5) ; also on sheet 5
S_P2C6: U22.Y25(P2_C6) ; also on sheet 5
S_P2C7: U22.Y26(P2_C7) ; also on sheet 5
S_P2C8: U22.V22(P2_C8) ; also on sheet 5
S_P2C9: U22.W23(P2_C9) ; also on sheet 5
S_PCLK1: U22.AE22(P_CLK1) ; also on sheet 4
S_PGOOD: R224.1 U40.8(2Y)
S_PIPESTAT0: TP46.1 U22.C6(RESERVED)
S_PIPESTAT1: TP45.1 U22.B5(RESERVED)
S_PIPESTAT2: TP44.1 U22.A4(RESERVED)
S_PMDINTZ: R144.2 U22.AE8(RESERVED)
S_POSENSE: R222.2 U22.P22(POSENSE) ; also on sheet 8
S_POWERGOOD: R210.2 R224.2 S_TP21.1 U22.T26(PWRGOOD)
S_RTCK: R107.1 R146.2
S_RTCK_OUT: R146.1 U22.E4(RTCK)
S_SCTLA_N: U22.J2(SCB_N) ; also on sheet 7
S_SCTLA_P: U22.J1(SCB_P) ; also on sheet 7
S_SCTLB_N: U22.V1(SCA_N) ; also on sheet 7
S_SCTLB_P: U22.V2(SCA_P) ; also on sheet 7
S_SEQ_AUX6: R161.1 U22.E26(SEQ_AUX6)
S_SEQ_AUX7: R162.1 U22.F26(SEQ_AUX7)
S_SEQ_INT1: R162.2 TP61.1 U22.G26(SEQ_INT1)
S_SEQ_INT2: R161.2 TP62.1 U22.H26(SEQ_INT2)
S_STATUS_GRN: R165.1 U22.AB12(HEARTBEAT)
S_STATUS_RED: R163.1 U22.AC11(FAULT_STATUS)
S_TDI: R117.2 R118.1 U22.N25(TDI)
S_TDO1: R112.1 U22.N23(TDO1)
S_TDO2: R110.1 U22.N22(TDO2)
S_TRACECLK: TP48.1 U22.D7(RESERVED)
S_TRACESYNC: TP47.1 U22.A5(RESERVED)
S_TSTPT0: TP43.1 U22.C2(RESERVED)
S_TSTPT1: TP42.1 U22.D3(RESERVED)
S_TSTPT2: TP41.1 U22.E6(RESERVED)
S_TSTPT3: TP40.1 U22.D5(RESERVED)
S_TSTPT4: TP39.1 U22.E7(RESERVED)
S_TSTPT5: TP38.1 U22.C4(RESERVED)
S_TSTPT6: TP37.1 U22.B4(RESERVED)
S_TSTPT7: TP36.1 U22.E8(RESERVED)
S_UART0_CTSZ: J17.4 R147.1 U22.AE2(UART0_CTSZ)
S_UART0_RTSZ: J17.5 U22.AD2(UART0_RTSZ)
S_UART0_RXD: J17.3 U22.AD1(UART0_RXD)
S_UART0_TXD: J17.2 U22.AB3(UART0_TXD)
SEQ_SYNC: R121.2 R122.2 U22.AB9(SEQ_SYNC)
SLAVE_ASIC: R159.1 U22.V26(CTRL_MODE_CFG)
SLAVE_INT: R160.1 U13.V25(SLV_CTRL_PRST) U22.V25(SLV_CTRL_PRST)
SPGAND_2B_IN: R227.2 U40.10(2B)
SPGAND_2C_IN: R226.2 U40.12(2C)
SRSTZ: J9.15 R108.2 U20.4(\~{_RESE}T) U21.2(A)
SSP0_CLK: R77.2 U22.AD4(SSP0_CLK) ; also on sheet 5 7
SSP0_CSZ0_DAD1: R81.2 ; also on sheet 7
SSP0_CSZ1_DMD: R80.2 ; also on sheet 7
SSP0_CSZ2_FPGA: R79.2 ; also on sheet 5
SSP0_CSZ4_SLAVE: R158.1 U13.U26(SSP0_CSZ4_SLV) U22.U26(SSP0_CSZ4_SLV)
SSP0_CSZ5_DAD2: R138.2 ; also on sheet 7
SSP0_RXD_S2M: R76.2 U13.AD5(SSP0_RXD) U22.AB7(SSP0_TXD) ; also on sheet 5 7
SSP0_TXD_M2S: R78.2 U22.AD5(SSP0_RXD) ; also on sheet 5 7
TCK: J9.9 J11.5 R102.2 R104.1 U13.N24(TCK) U22.N24(TCK)
TDI: J9.5 J11.2 R98.2 U13.N25(TDI)
TDO1: J11.4 R111.2 R112.2
TDO2: J9.13 R101.2 R109.2 R110.2
TMS1: J11.3 U13.P25(TMS1) U22.P25(TMS1)
TMS2: J9.7 R99.2 U13.P26(TMS2) U22.P26(TMS2)
TRIG1_IN_CON: J23.2 U34.2
TRIG1_IN_T: U33.3(A) U34.4
TRIG1_OUT_CON: J27.2 U37.4(B)
TRIG2_IN_CON: J23.5 U36.2
TRIG2_IN_T: U35.3(A) U36.4
TRIG2_OUT_CON: J27.5 U38.4(B)
TRIGGER_IN1: R201.1 S_TP15.1 U13.AF7(TRIG_IN_1) U22.AF7(TRIG_IN_1) U33.4(B)
TRIGGER_IN2: R203.1 S_TP16.1 U13.H25(TRIG_IN_2) U22.H25(TRIG_IN_2) U35.4(B)
TRIGGER_OUT_AUX0: R205.1 S_TP17.1 U13.E20(TRIG_OUT_1) U37.3(A)
TRIGGER_OUT_AUX1: R207.1 S_TP18.1 U13.D22(TRIG_OUT_2) U38.3(A)
TRSTZ: J11.1 R97.2 U13.M23(TRSTZ) U19.4(Y) U22.M23(TRSTZ)
TRSTZ_IN: J9.3 R103.1 U19.1(~{OE})
USB_DAT_N: J8.2 R85.1 U15.3(NC3) U15.4(B)
USB_DAT_P: J8.3 R84.2 R86.1 U15.1(NC1) U15.6(A)
USB_SENSE: R84.1 TP17.1 U14.4(Y)
USB_VBUS: J8.1 R82.1 U14.2(A)
N20224398: R119.1 U13.M24(ICTSEN)
N20250700: R137.1 U13.AF8(RESERVED)
N20263361: D6.2(ANODE) R129.2
N20271735: D7.2(ANODE) R133.2
N20345555: D9.2(ANODE) R165.2
N20345600: D8.2(ANODE) R163.2
N20518299: R202.2 U35.5(DIR)
N20519329: R200.2 U33.5(DIR)
N20522932: R204.2 U37.5(DIR)
N20523509: R206.2 U38.5(DIR)
N21371449: D12.2(ANODE) R209.2
N21371451: Q2.G R212.2
N21371492: D12.1(CATHODE) Q2.D

Not connected (* = marked no-connect by the designer): J9 17* 19*; J26 4(P4); U13 A6(PM_BLSZ_0)* A19(RESERVED)* A20(RESERVED)* AB4(RESERVED)* AB10(RESERVED)* AB11(RESERVED)* AC9(RESERVED)* AC10(RESERVED)* AD9(RESERVED)* AD10(RESERVED)* AD11(RESERVED)* AD12(RESERVED)* AE9(RESERVED)* AE10(RESERVED)* AE11(RESERVED)* AF10(RESERVED)* AF11(RESERVED)* AF23(P_CLK3)* B6(PM_BLSZ_1)* B23(RESERVED)* B24(RESERVED)* C19(RESERVED)* C22(RESERVED)* C23(RESERVED)* C26(RESERVED)* D19(RESERVED)* D21(RESERVED)* D25(RESERVED)* D26(RESERVED)* E3(RESERVED)* E18(RESERVED)* E23(RESERVED)* E24(RESERVED)* F22(RESERVED)* F23(RESERVED)* F25(RESERVED)* G22(RESERVED)* G23(RESERVED)* G25(RESERVED)* H22(RESERVED)* H23(RESERVED)* H24(RESERVED)* J22(RESERVED)* K23(RESERVED)* K24(RESERVED)* N26(MOSCN)* T22(RESERVED)* T25(CTRL_ARSTZ)* U22(P2_VSYNC)* U23(RESERVED)* W24(P_DATAEN2)* W25(P_CLK2)* W26(P2_HSYNC)*; U16 1(NC)* 27(NC)* 28(NC)* 30(NC)* 53(NC)* 55(NC)* 56(NC)*; U17 1(NC)* 27(NC)* 28(NC)* 30(NC)* 53(NC)* 55(NC)* 56(NC)*; U18 1(NC)* 27(NC)* 28(NC)* 30(NC)* 53(NC)* 55(NC)* 56(NC)*; U22 A19(RESERVED)* A20(RESERVED)* A21(GPIO_PWM_0)* A22(GPIO_PWM_2)* A23(GPIO_PWM_3)* AB4(RESERVED)* AB6(SSP0_CSZ_1)* AB8(DADADDR_0)* AB10(RESERVED)* AB11(RESERVED)* AB13(AFE_IRQ)* AC3(SSP0_CSZ_2)* AC5(SSP0_CSZ_0)* AC7(DADSEL_0)* AC9(RESERVED)* AC10(RESERVED)* AC12(AFE_ARSTZ)* AD6(DADADDR_3)* AD7(DADMODE_1)* AD9(RESERVED)* AD10(RESERVED)* AD11(RESERVED)* AD12(RESERVED)* AE4(DADSEL_1)* AE5(DADADDR_2)* AE6(DADMODE_0)* AE7(DADOEZ)* AE9(RESERVED)* AE10(RESERVED)* AE11(RESERVED)* AF4(DADADDR_1)* AF5(DADSTRB)* AF6(OCLKA)* AF10(RESERVED)* AF11(RESERVED)* AF23(P_CLK3)* B21(GPIO_PWM_1)* B22(I2C2_SCL)* B23(RESERVED)* B24(RESERVED)* B26(RED_LED_EN)* C5(USB_DAT_N)* C19(RESERVED)* C21(I2C2_SDA)* C22(RESERVED)* C23(RESERVED)* C25(GRN_LED_EN)* C26(RESERVED)* D6(USB_DAT_P)* D19(RESERVED)* D20(I2C1_SCL)* D21(RESERVED)* D24(BLU_LED_EN)* D25(RESERVED)* D26(RESERVED)* E3(RESERVED)* E18(RESERVED)* E19(I2C1_SDA)* E23(RESERVED)* E24(RESERVED)* E25(USB_ENZ)* F22(RESERVED)* F23(RESERVED)* F25(RESERVED)* G22(RESERVED)* G23(RESERVED)* G25(RESERVED)* H22(RESERVED)* H23(RESERVED)* H24(RESERVED)* J22(RESERVED)* J23(TEST_FUNC_1)* J24(TEST_FUNC_2)* J25(TEST_FUNC_3)* J26(TEST_FUNC_4)* K22(TEST_FUNC_5)* K23(RESERVED)* K24(RESERVED)* N26(MOSCN)* T22(RESERVED)* T25(CTRL_ARSTZ)* U22(P2_VSYNC)* U23(RESERVED)* W24(P_DATAEN2)* W25(P_CLK2)* W26(P2_HSYNC)*; U34 1*; U36 1*; U40 3(NC)* 11(NC)*; U41 2(NC2)* 5(NC5)*; U42 7(NC7)*

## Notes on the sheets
sheet 9
- Must have pulldown on Slave
  pin V26 for normal operation.
  Pin V25 of Master and Slave
  Controller must be tied
  together for proper operation
- Must connect pin
  E26 to H26, and
  pin F26 to G26 for
  normal operation
- Slave Controller I2C, GPIOs
sheet 10
- UART debug message port,
  not needed for production
- Slave Controller Reset, OSC, JTAG, UART0, SSP Port
sheet 11
- Swap A/B channel, and buses' bit order for
  ease of routing to flex connector
- Slave Video Input, DMD Output
sheet 12
- Use external voltage reference
  or on board 3.3V/1.8V supply
- Input Trigger 1 to controller
- Input Trigger Port
- Input Trigger 2 to controller
- Use external voltage reference
  or on board 3.3V/1.8V supply
- Output Trigger Port
- To LED driver board
- Input/Output Trigger and LED Driver Interface
sheet 13
- Per controller spec (Fig. 3), POWERGOOD has no
  impact on operation for 60ms after rising
  edge of POSENSE. In other words, during
  power up, controller will ignore the state of PG
  until the internal PLL is locked (require up to 60ms).
  Controller will then sample the PG input to begin
  normal operation.
  During power down, POSENSE has to remain
  valid high for at least 500us after PG is deasserted
  to allow controller to complete the DMD parking procedure.
  The 500+ uF input caps on 12V would ensure
  the power monitor to trip at ~11V to deassert PG
  while keeping regulators operational to maintain
  POSENSE for > 500us.
- D
- FDV303N
- G
- S
- Install jumper to hold Slave Controller
  in reset for Single Controller operation
- Generate Powergood, POSENSE, Clocks
sheet 14
- Install jumper to
  hold controllers  in
  boot mode
- Must have pullup on
  Master pin V26 for
  normal operation.
  Pin V25 of Master and
  Slave Controller must
  be tied together for
  proper operation
- GPIO User Connector
- Must connect pin
  E26 to H26, and
  pin F26 to G26 for
  normal operation
- I2C Port 0
- I2C Port 1
- I2C Port 2
- Master I2C, LED driver interface, In/Out Triggers and GPIOs
sheet 15
- ARM Multi-ICE debug port
- Install R106 only if slave
  controller is not populated
  for single controller
  operation
- Install jumper to hold controllers in reset
- Install R109 only if slave
  controller is not populated
  for single controller
  operation
- Pullup on open-drain signal
  POWERGOOD found on page 27
- Install R111 only if slave
  controller is not populated
  for single controller
  operation
- Install R118 if using the JTAG boundary scan
  port to program the external flash memory with
  TI GUI's flash downloader. R117 is installed only
  if using the ARM Realview ICE debugger HW.
- SEQ_SYNC used to
  synchronize PWM sequences
  in multi-controller system
- JTAG Boundary scan port may be
  used to download flash image using
  USB-to-JTAG FTDI adapter board
- Master Controller Multi-ICE Port
sheet 16
- Tied open drain outputs together
- Refer to the DLPC900 datasheet
  for other memory configurations.
- Master Controller Flash Interface
sheet 17
- UART debug message port,
  not needed for production
- DNI
- Buffer to prevent host from detecting
  the USB slave before ARM finishes
  initialization
- Master Controller SSP0, UART0, USB, Reset, OSC
sheet 18
- Swap A/B channel, and buses' bit order for
  ease of routing to flex connector
- Note: RC Filtering required only for
  TI reference design's flex cable
  due to impedance mismatch
- Master Video Input, DMD & DAD Output
